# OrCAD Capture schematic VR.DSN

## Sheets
1 15 SENSOR: size B
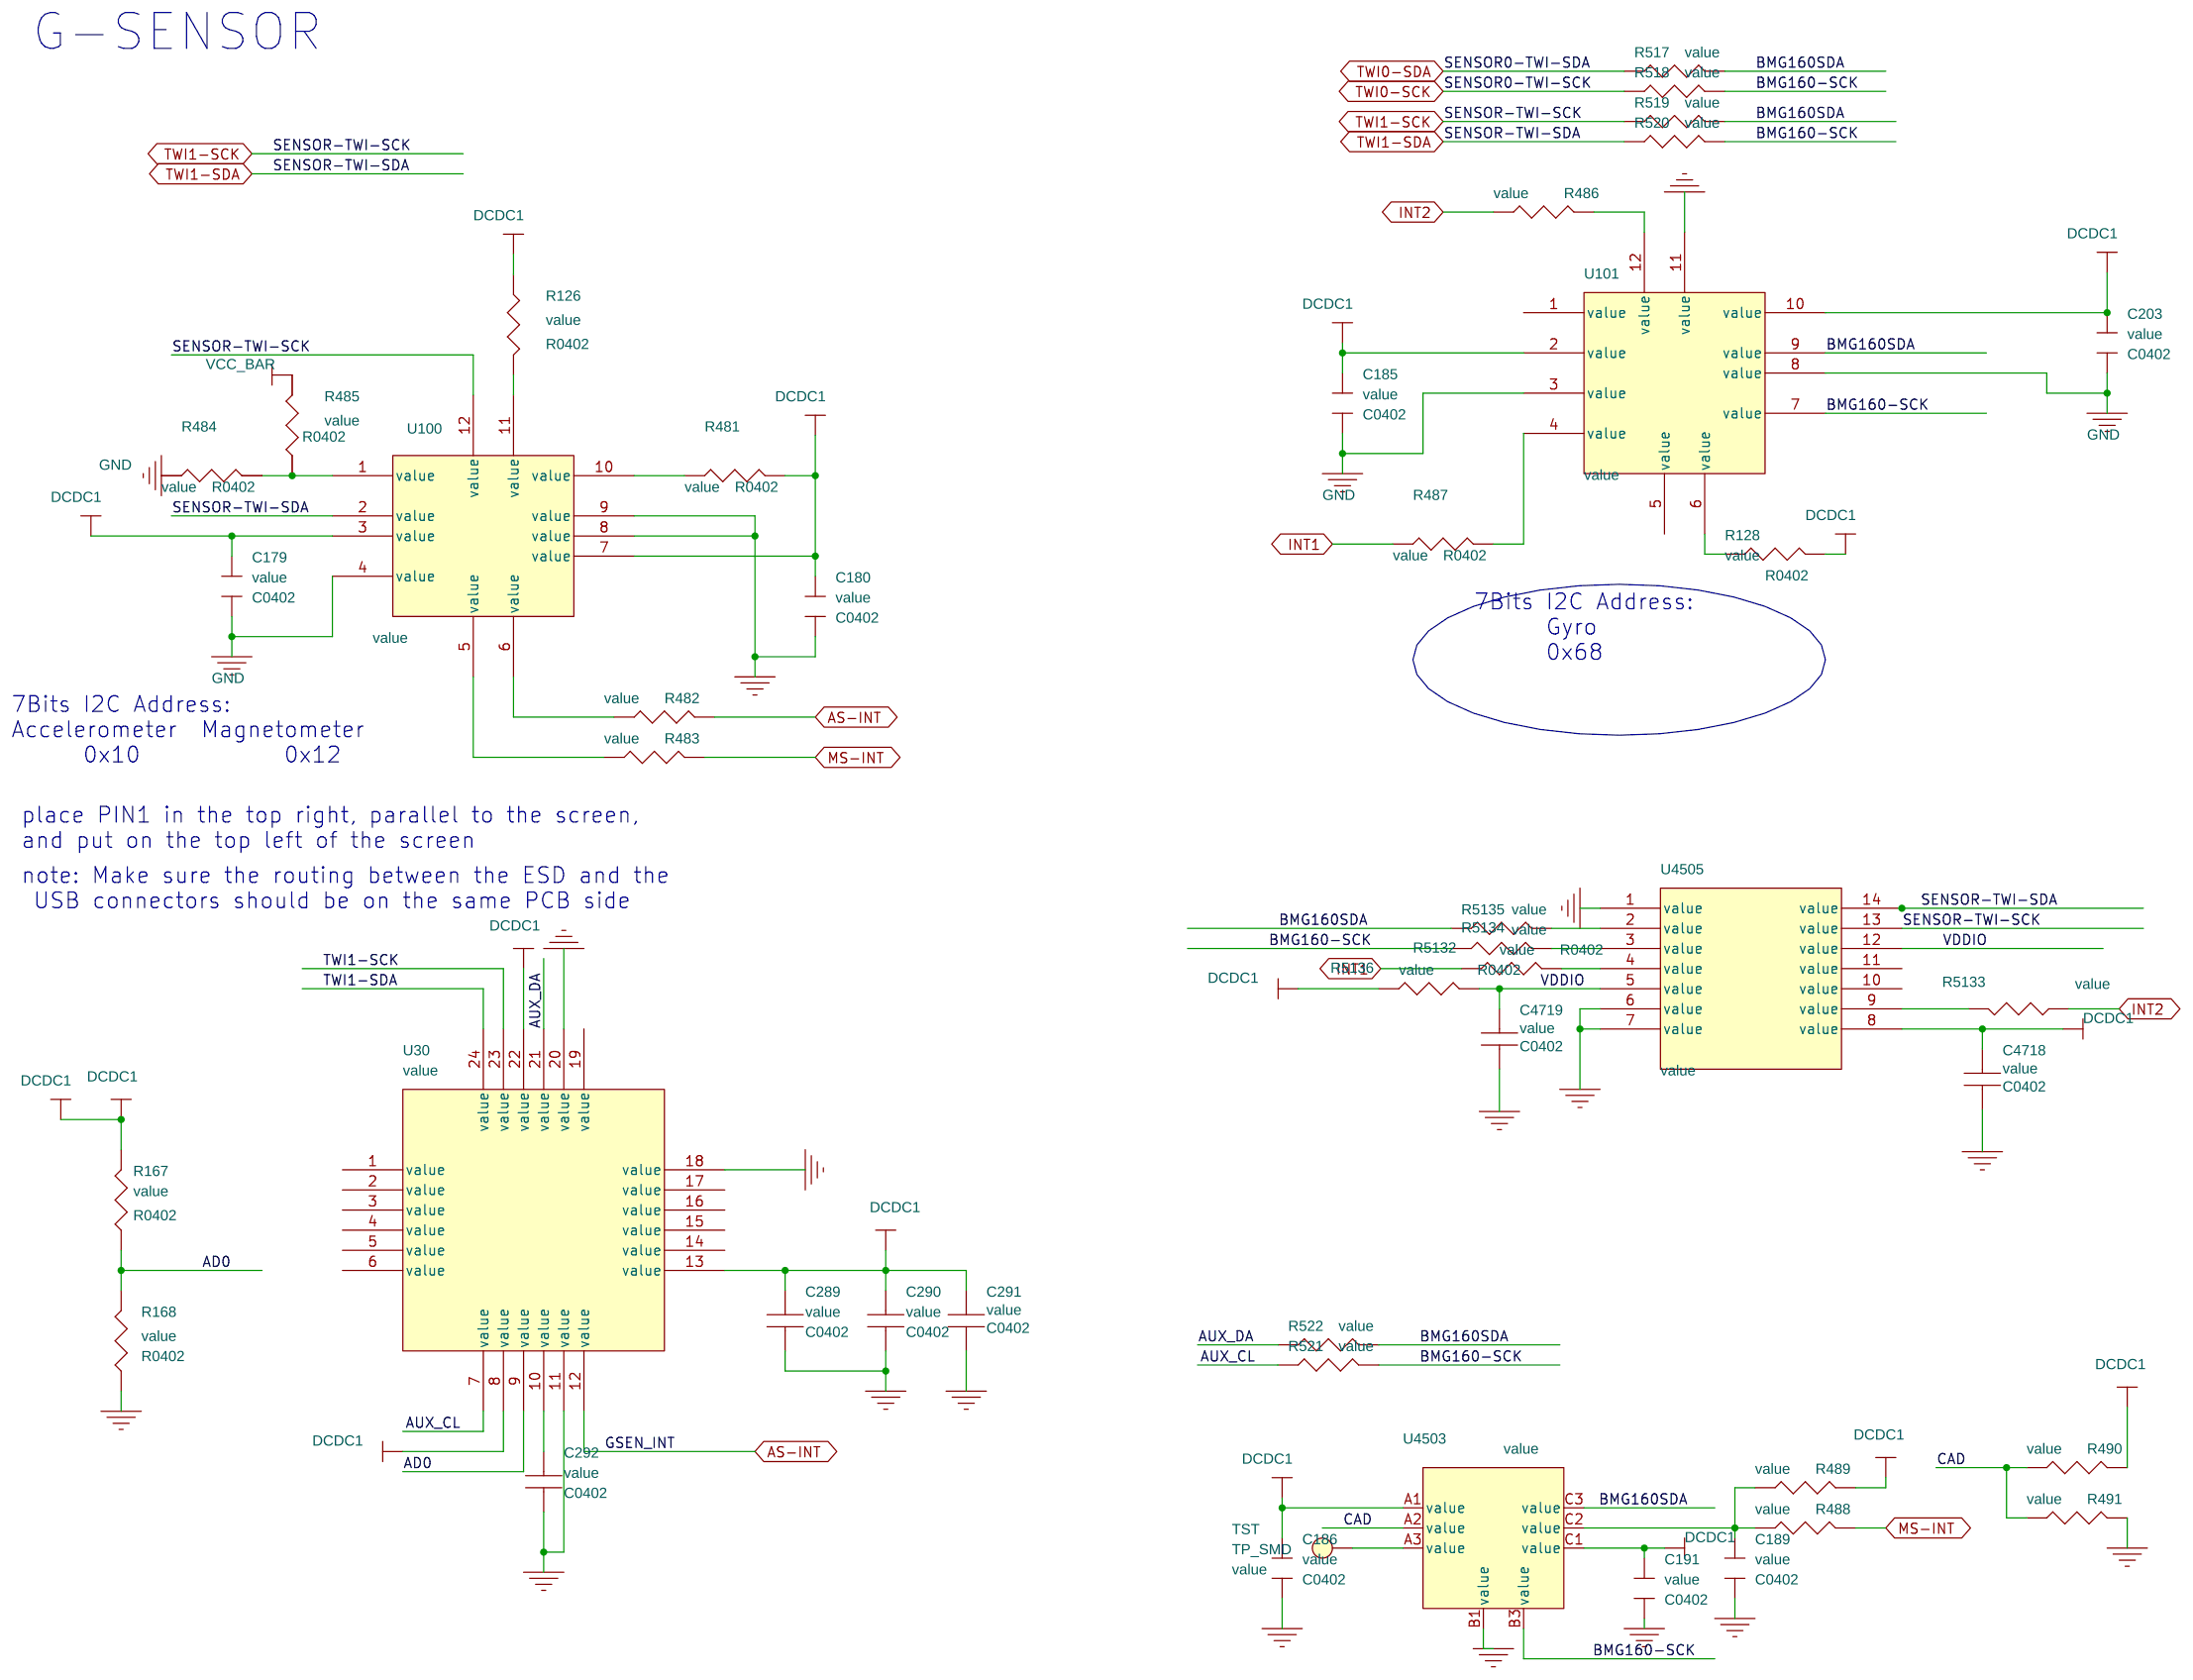
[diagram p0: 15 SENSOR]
2 09 CAMERA: size B
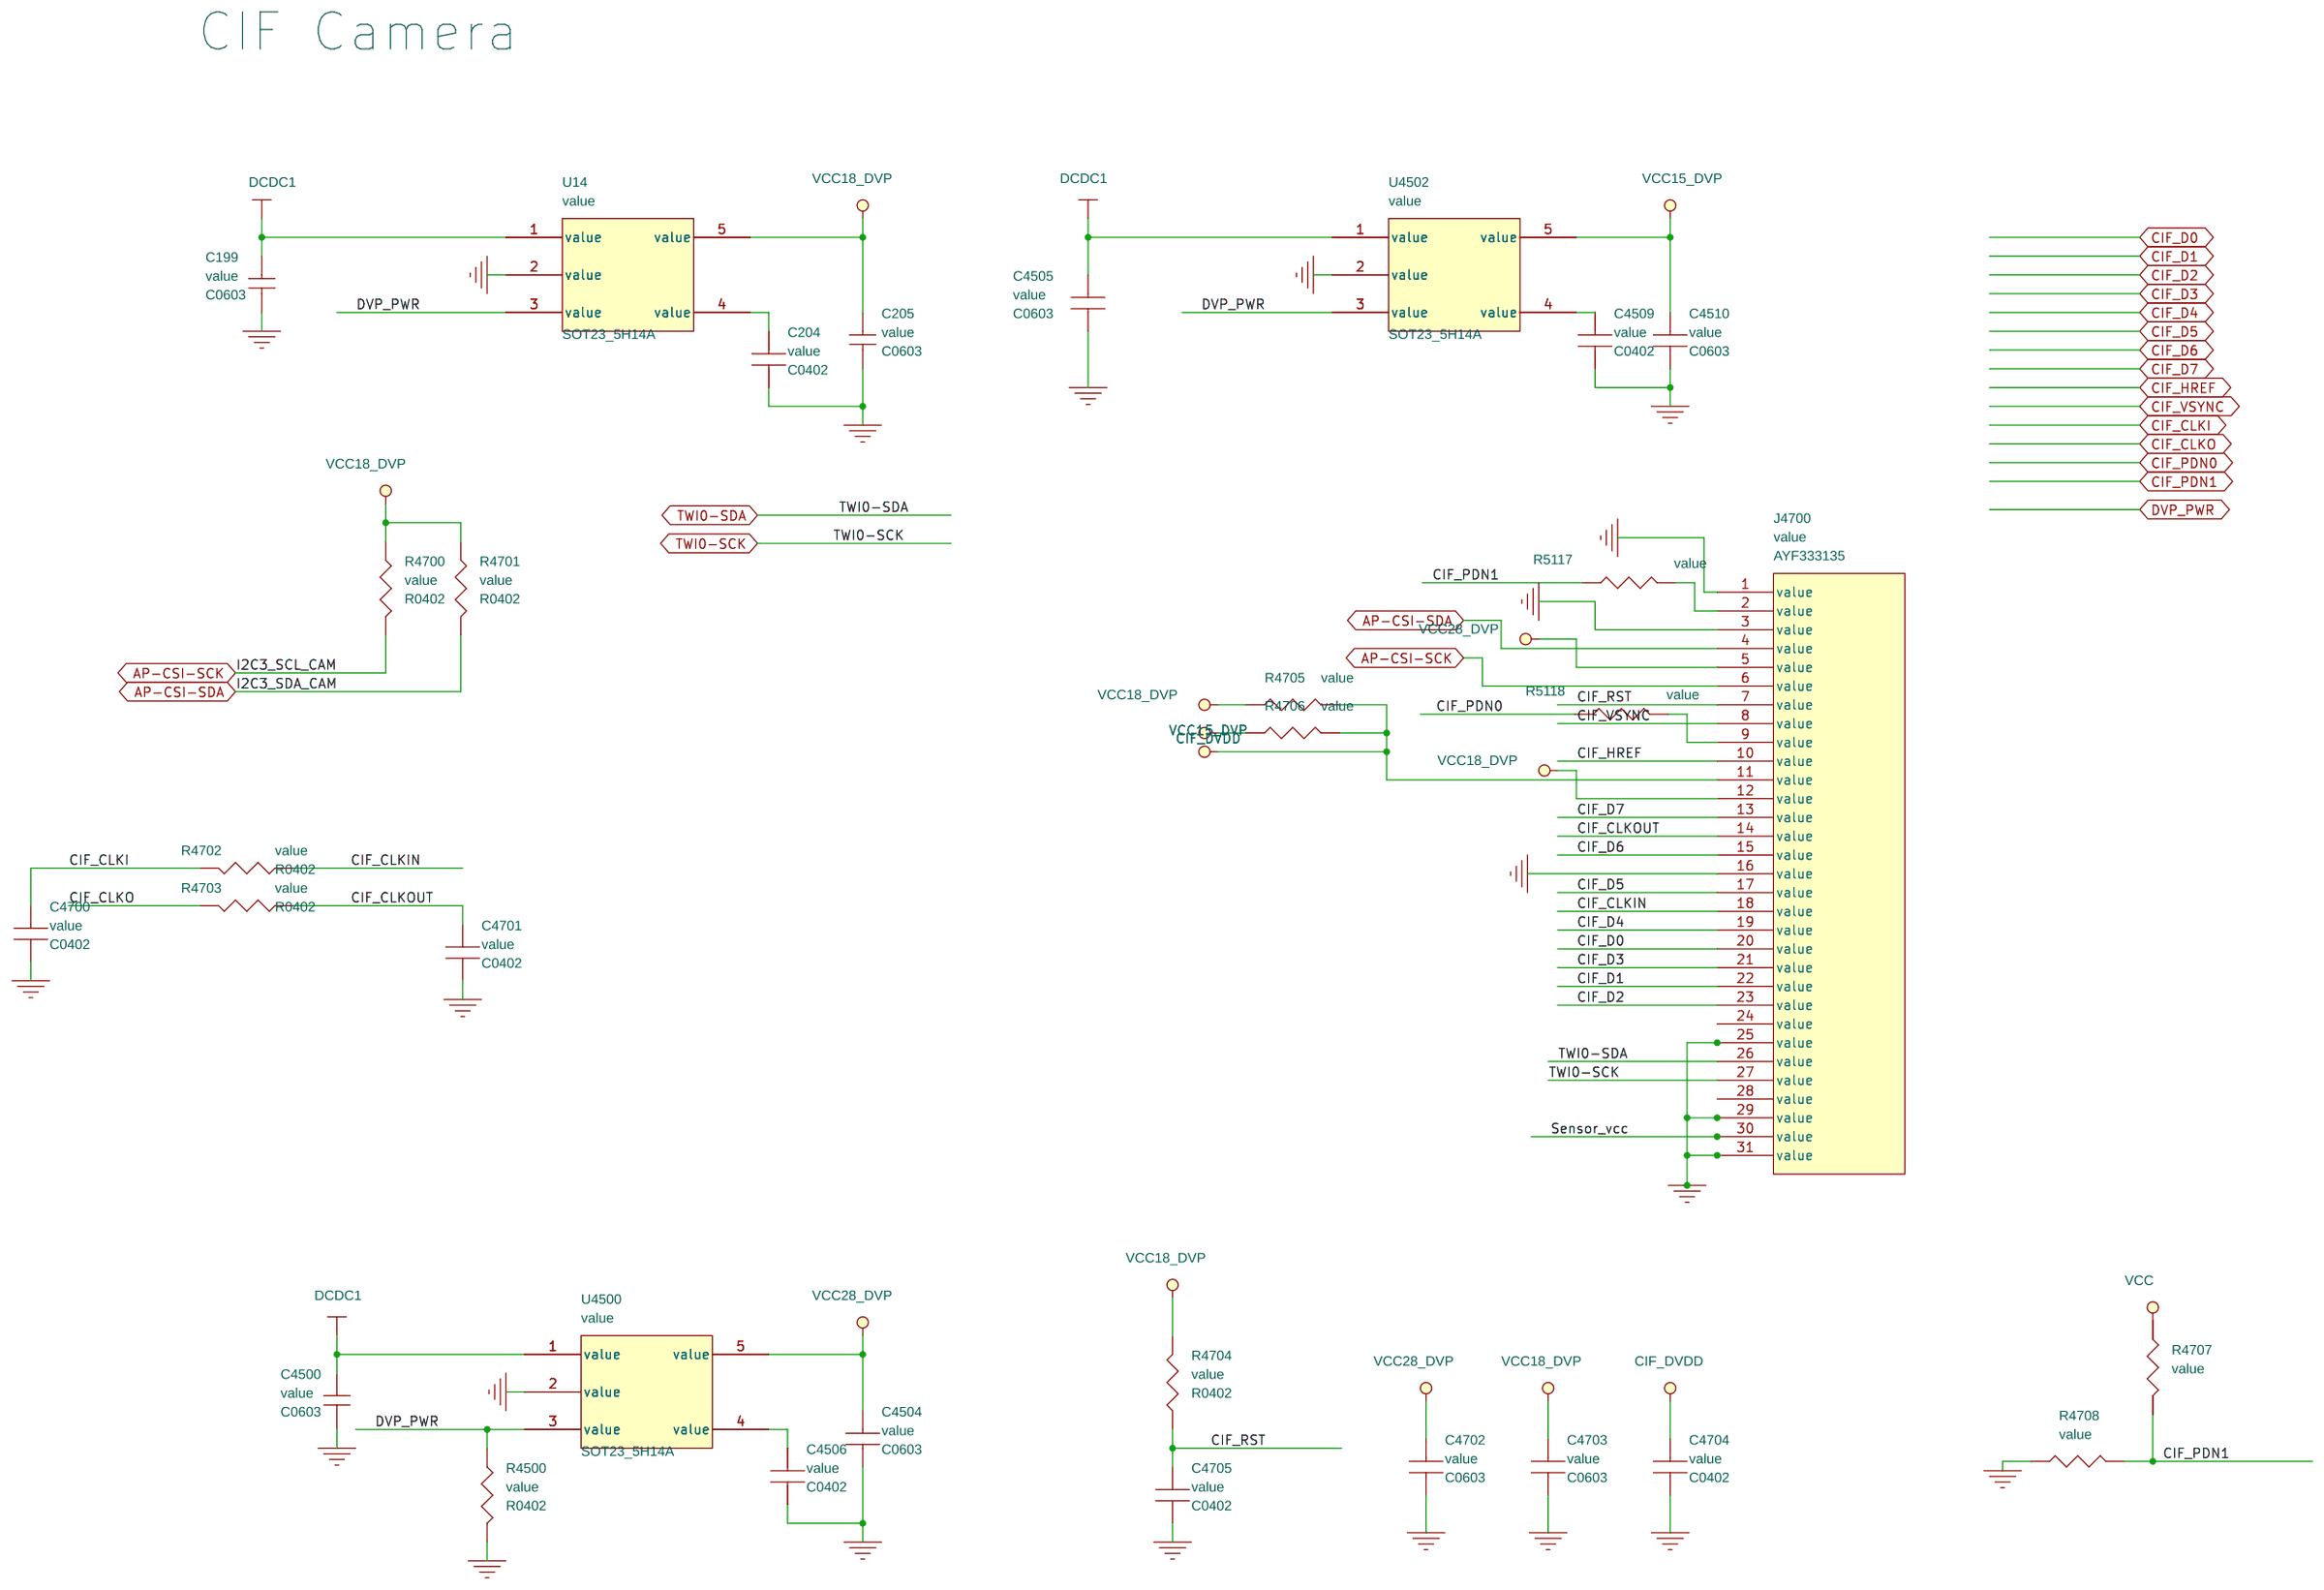
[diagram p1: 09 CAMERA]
3 14 TP: size A
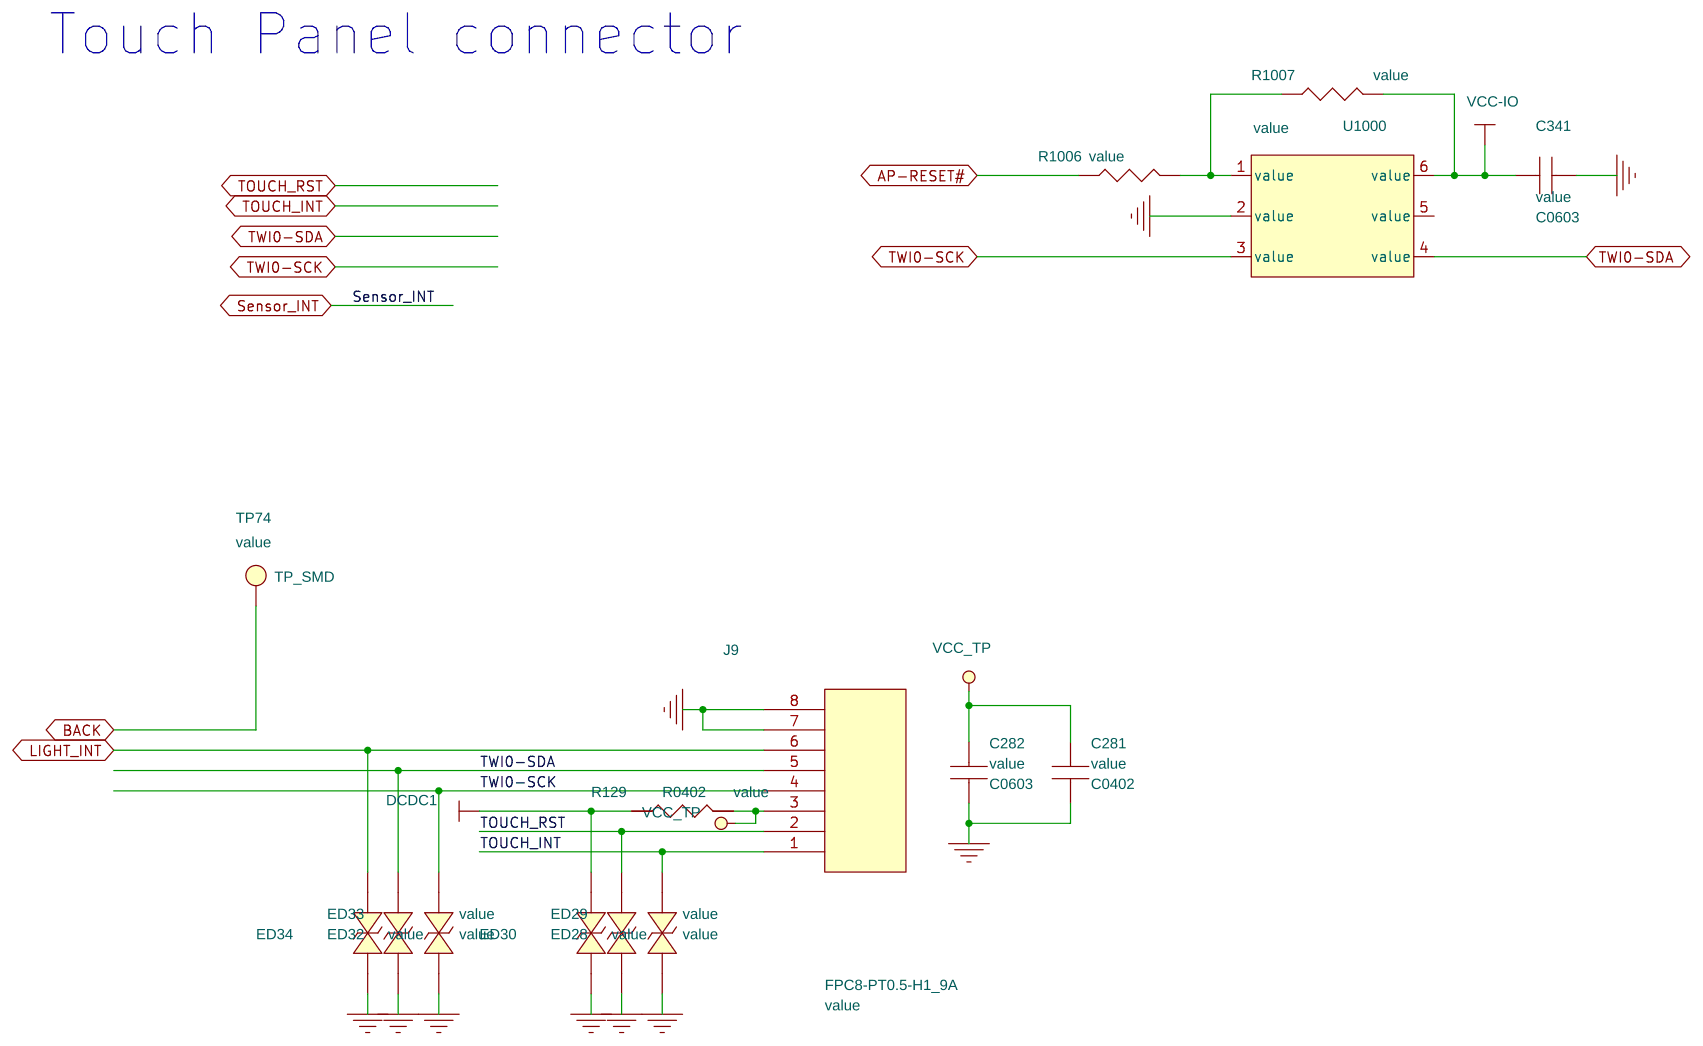
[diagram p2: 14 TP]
4 03 POWER TREE
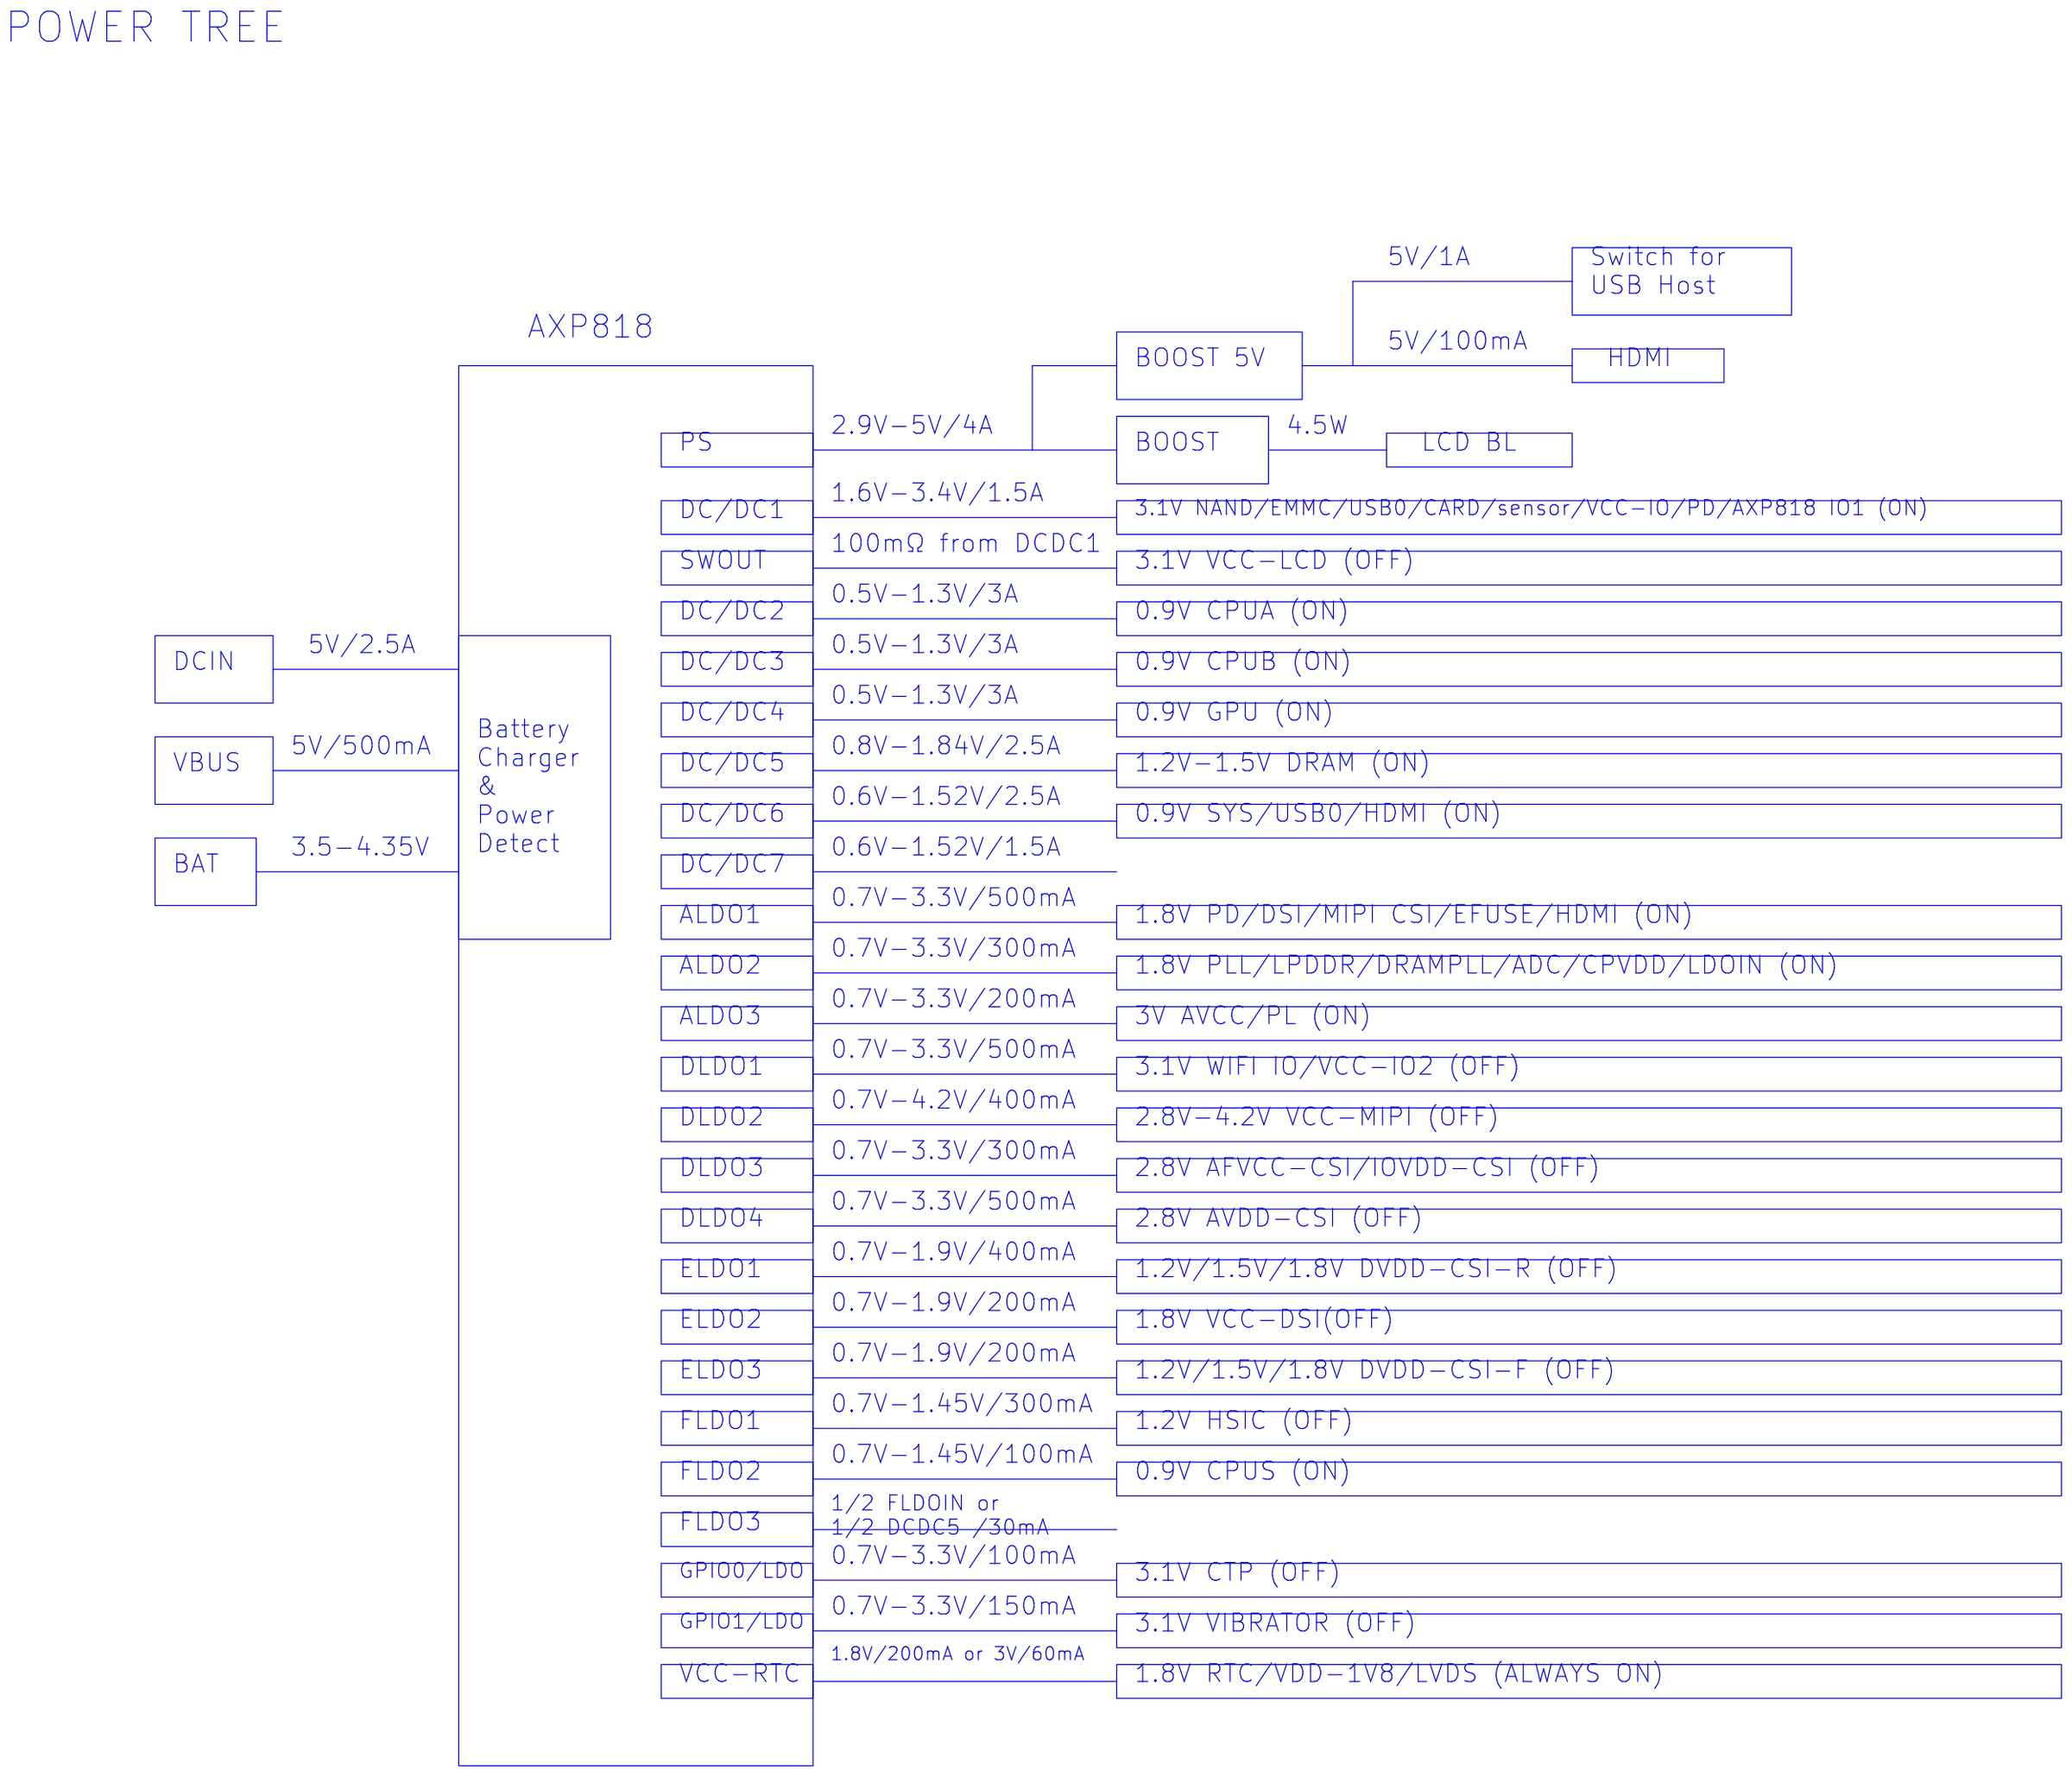
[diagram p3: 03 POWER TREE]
5 05 LPDDR3_32X1: size A3
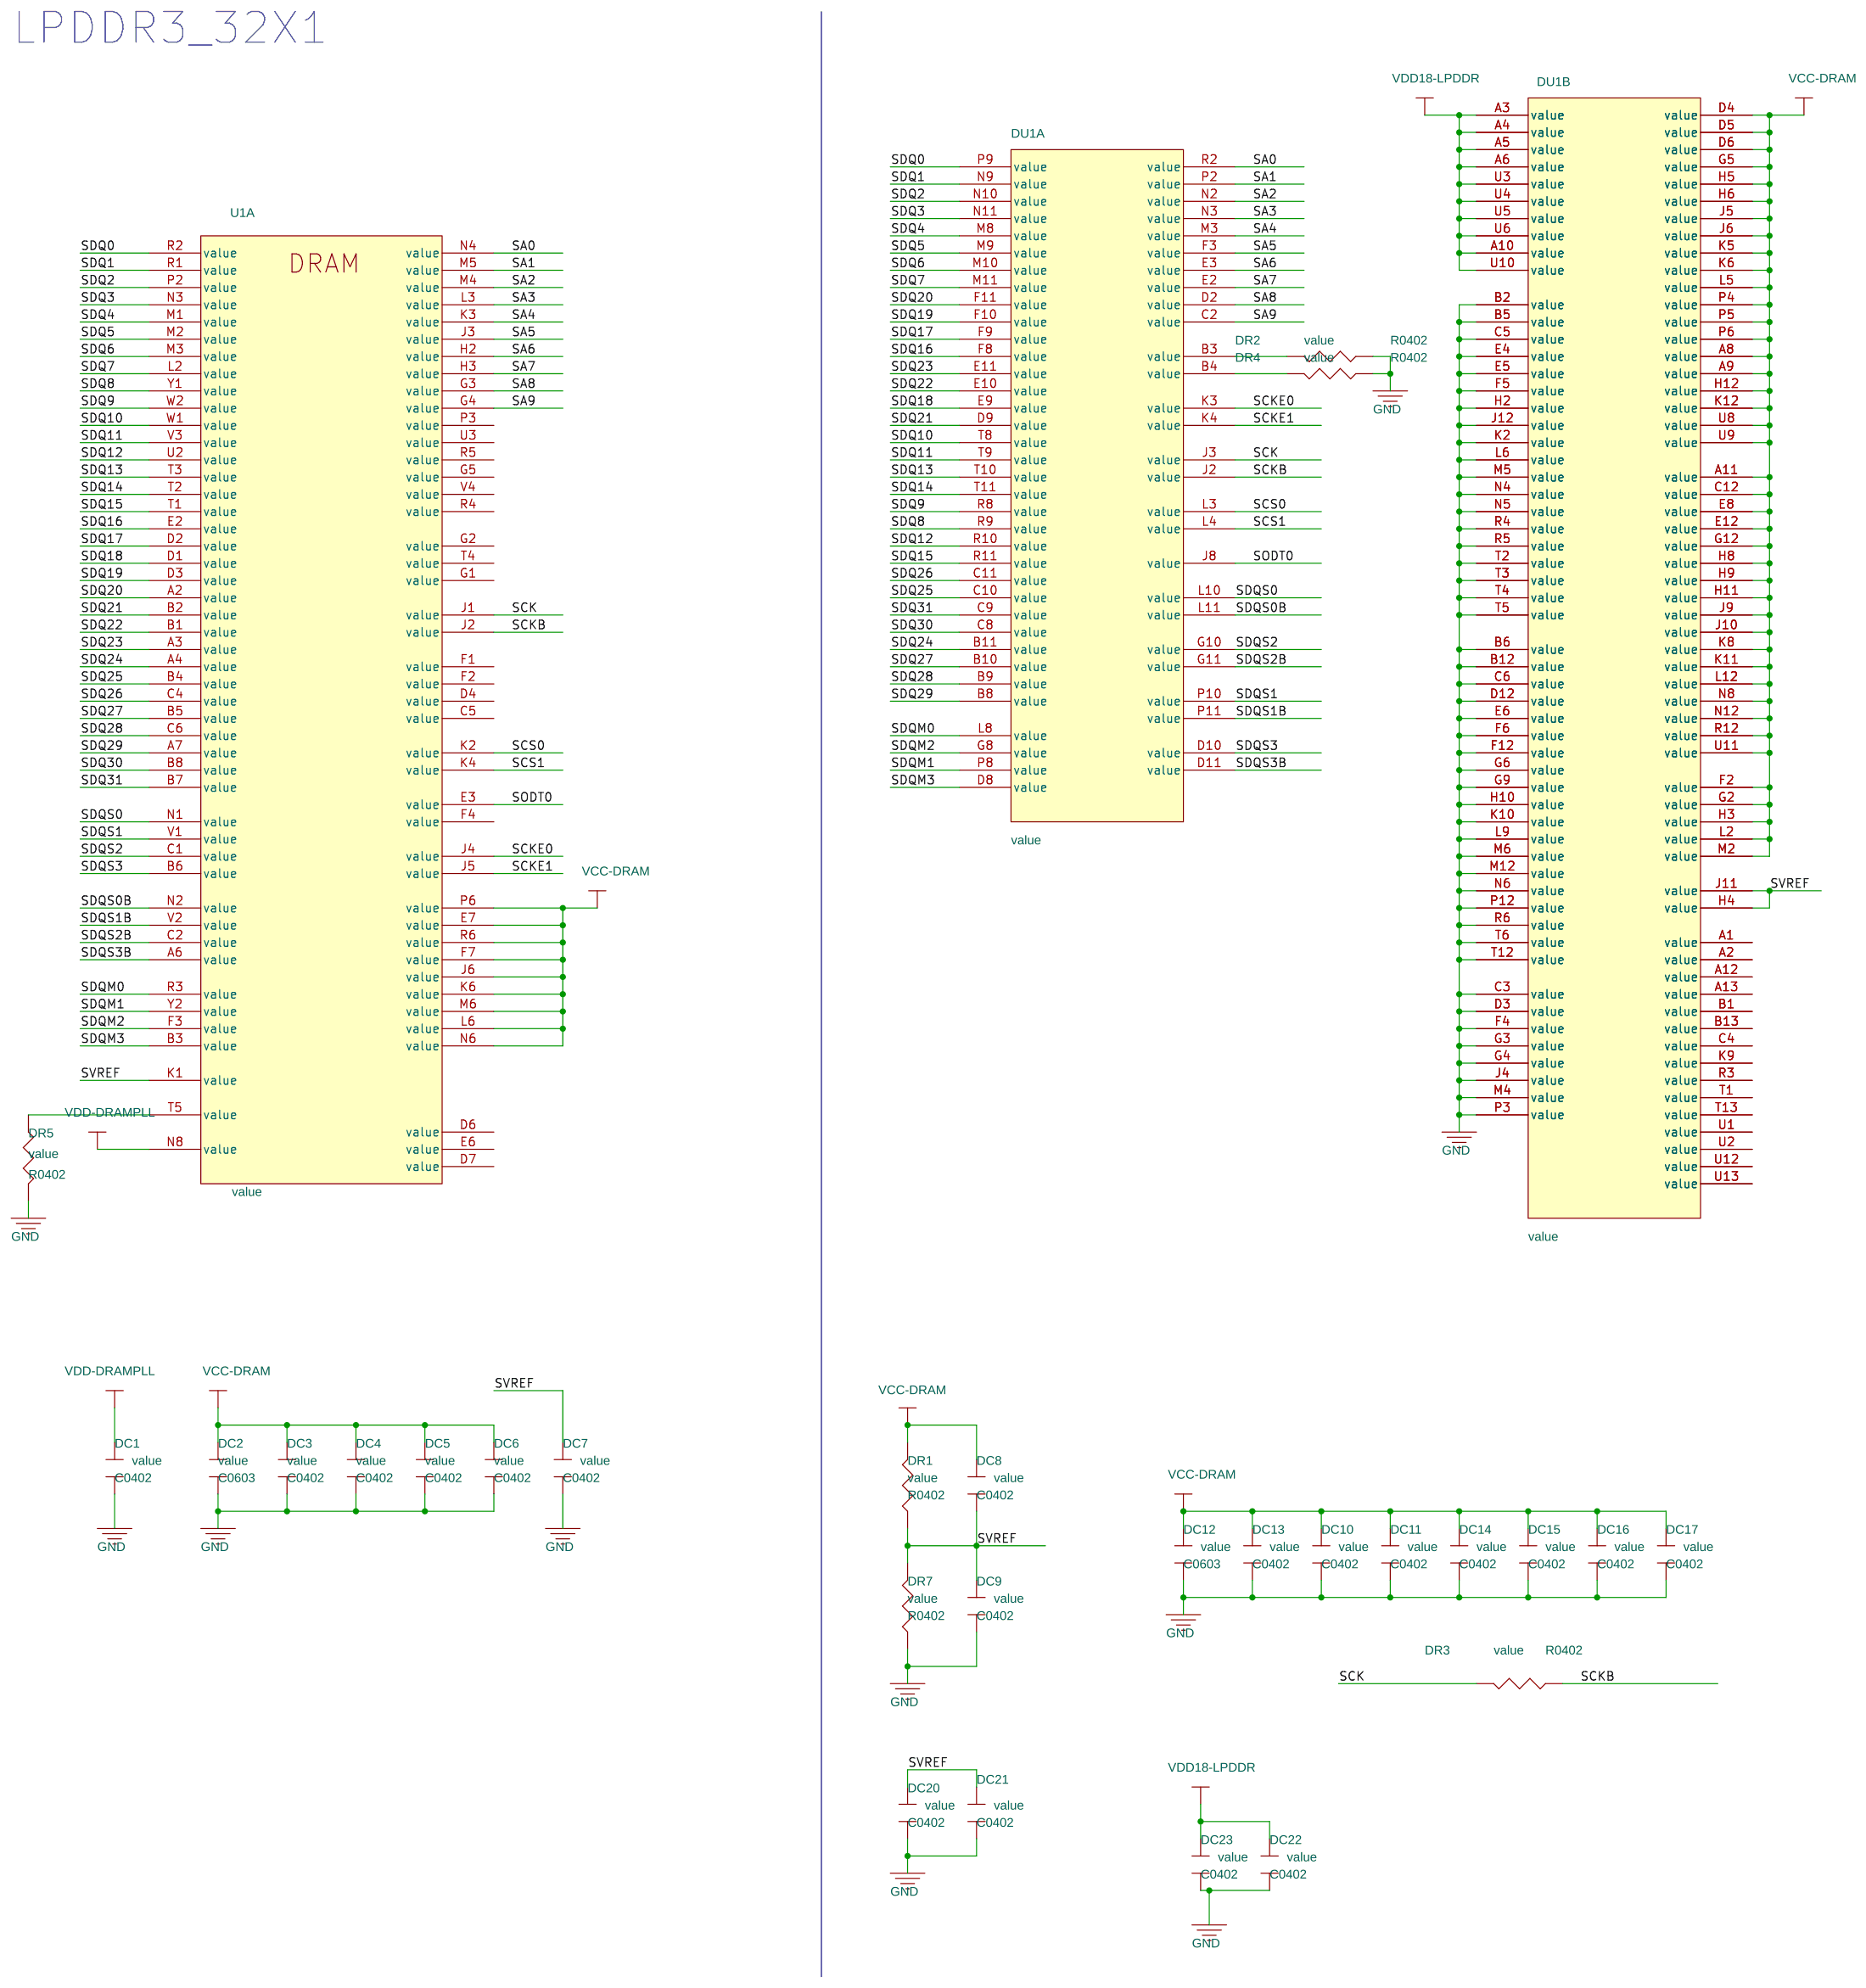
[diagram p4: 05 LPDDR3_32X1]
6 06 CPU: size A3
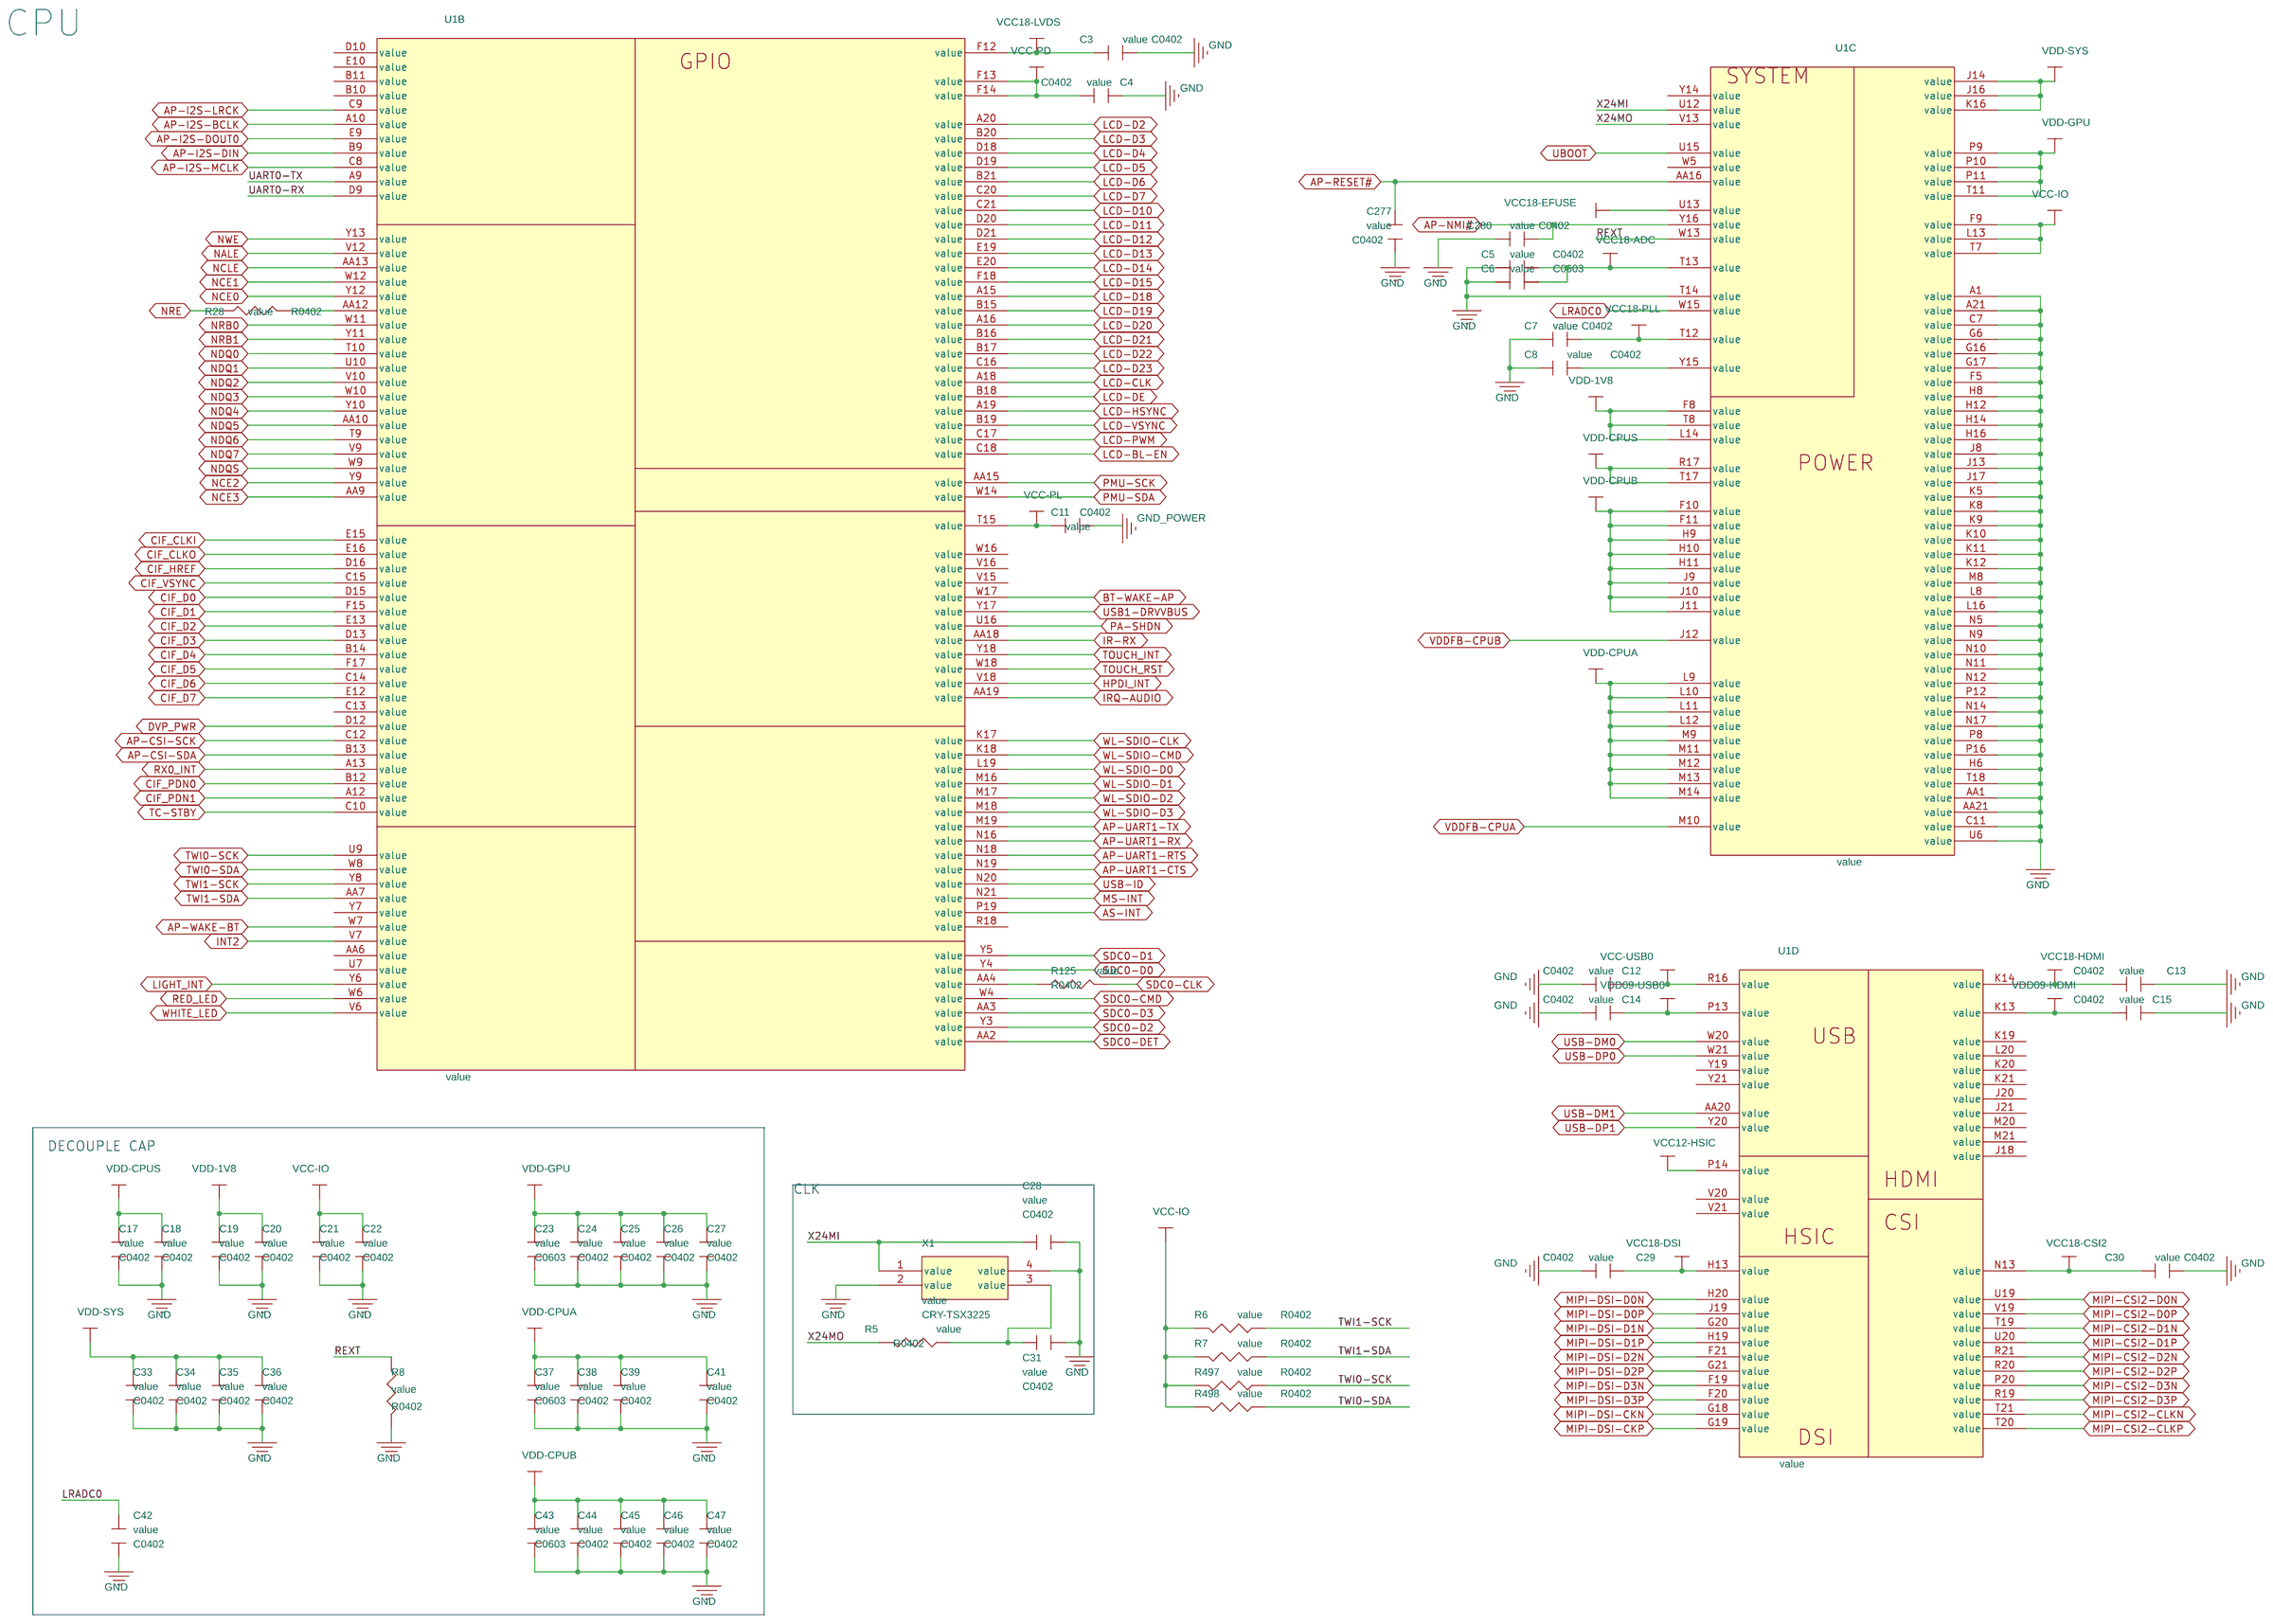
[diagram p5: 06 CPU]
7 07 POWER: size A3
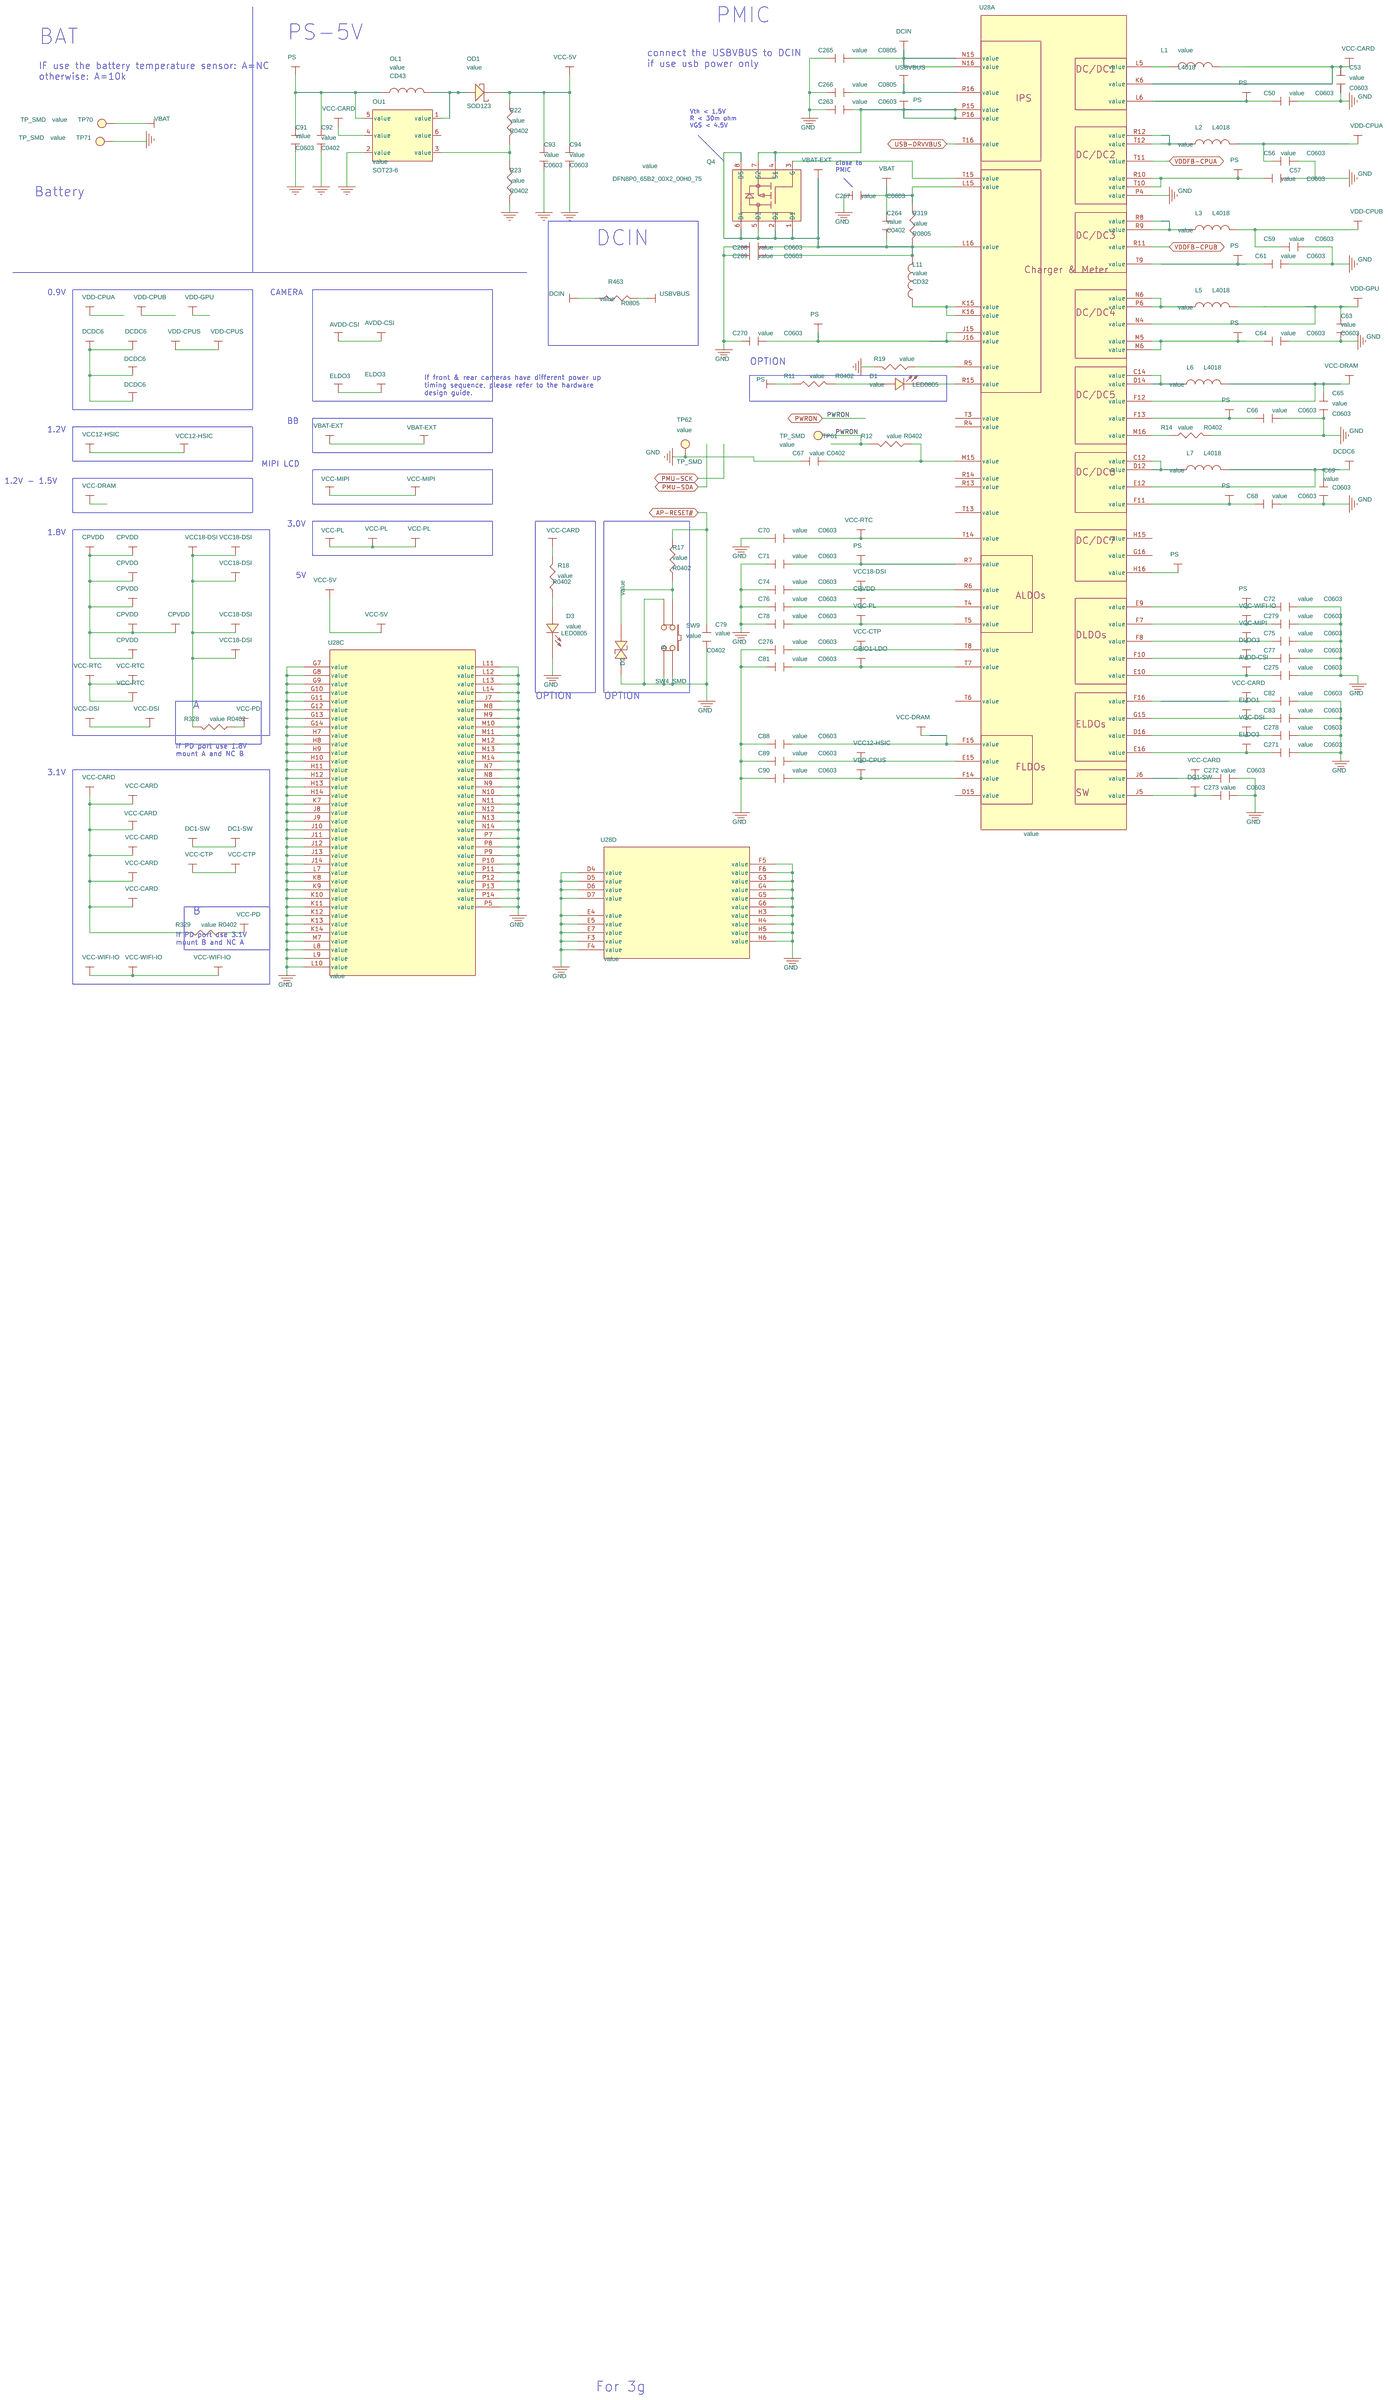
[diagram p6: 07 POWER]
8 08 NAND-eMMC: size A3
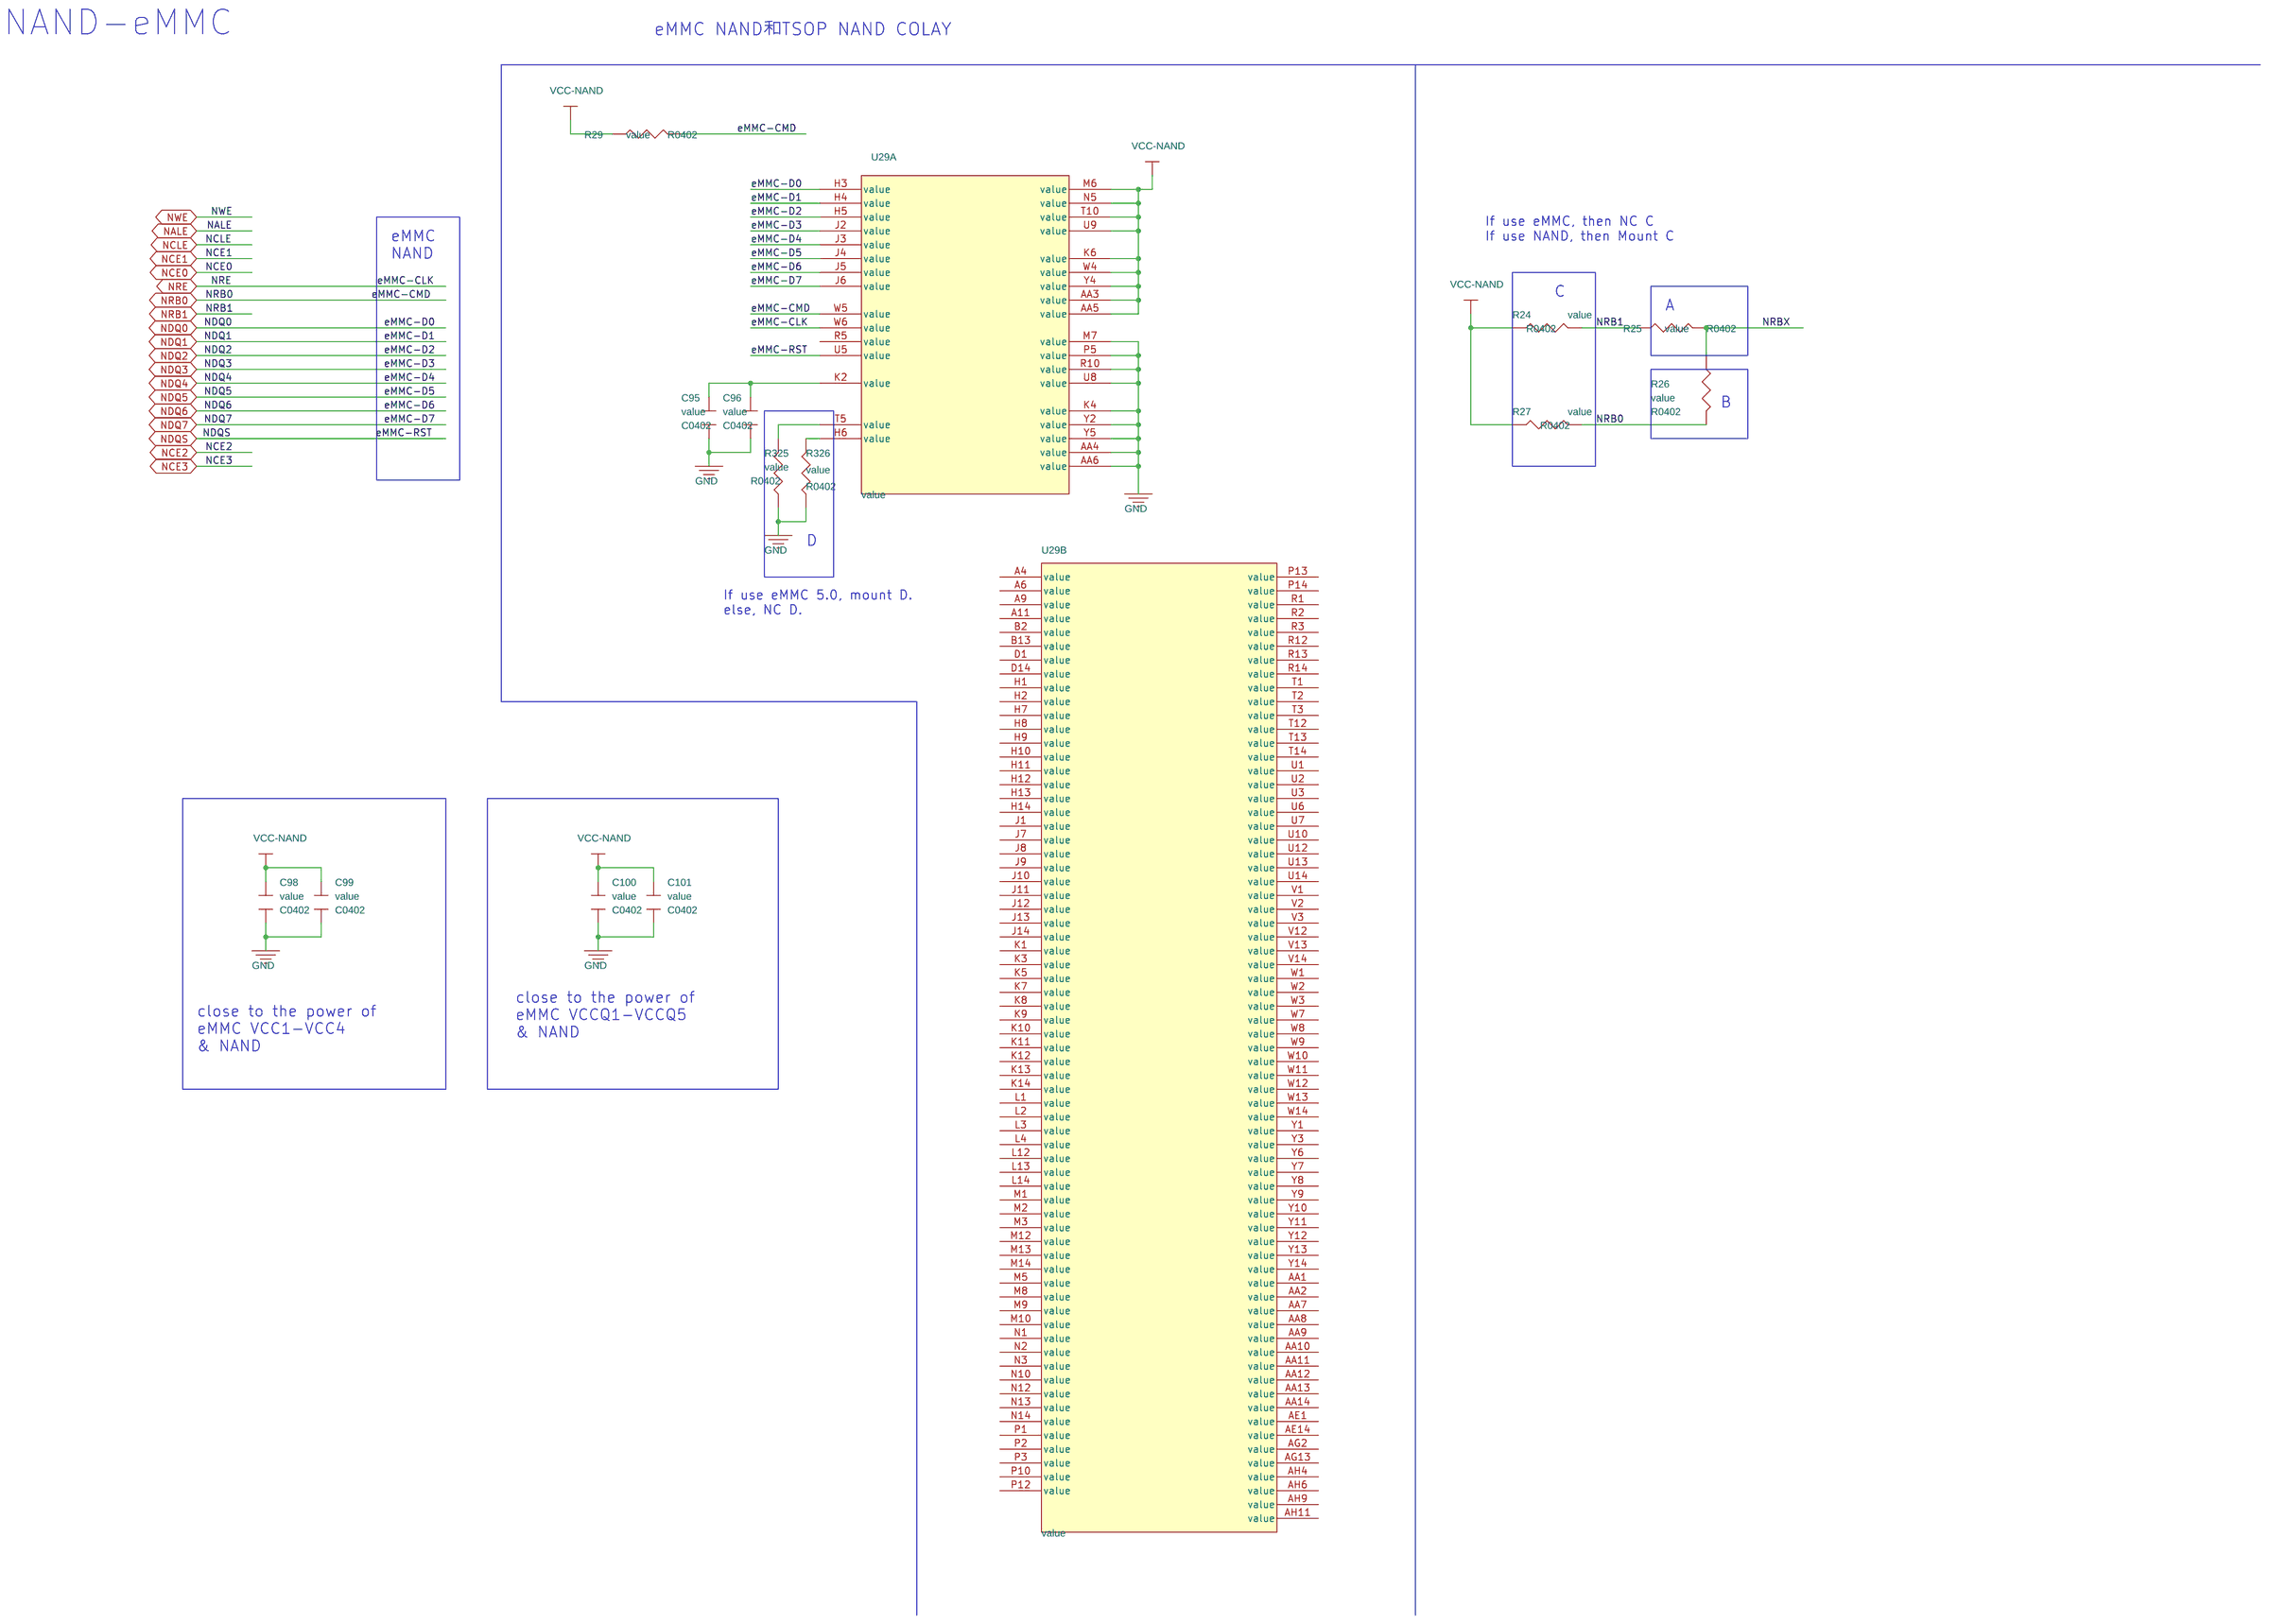
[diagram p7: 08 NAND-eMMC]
9 10 MIPI DSI: size Custom
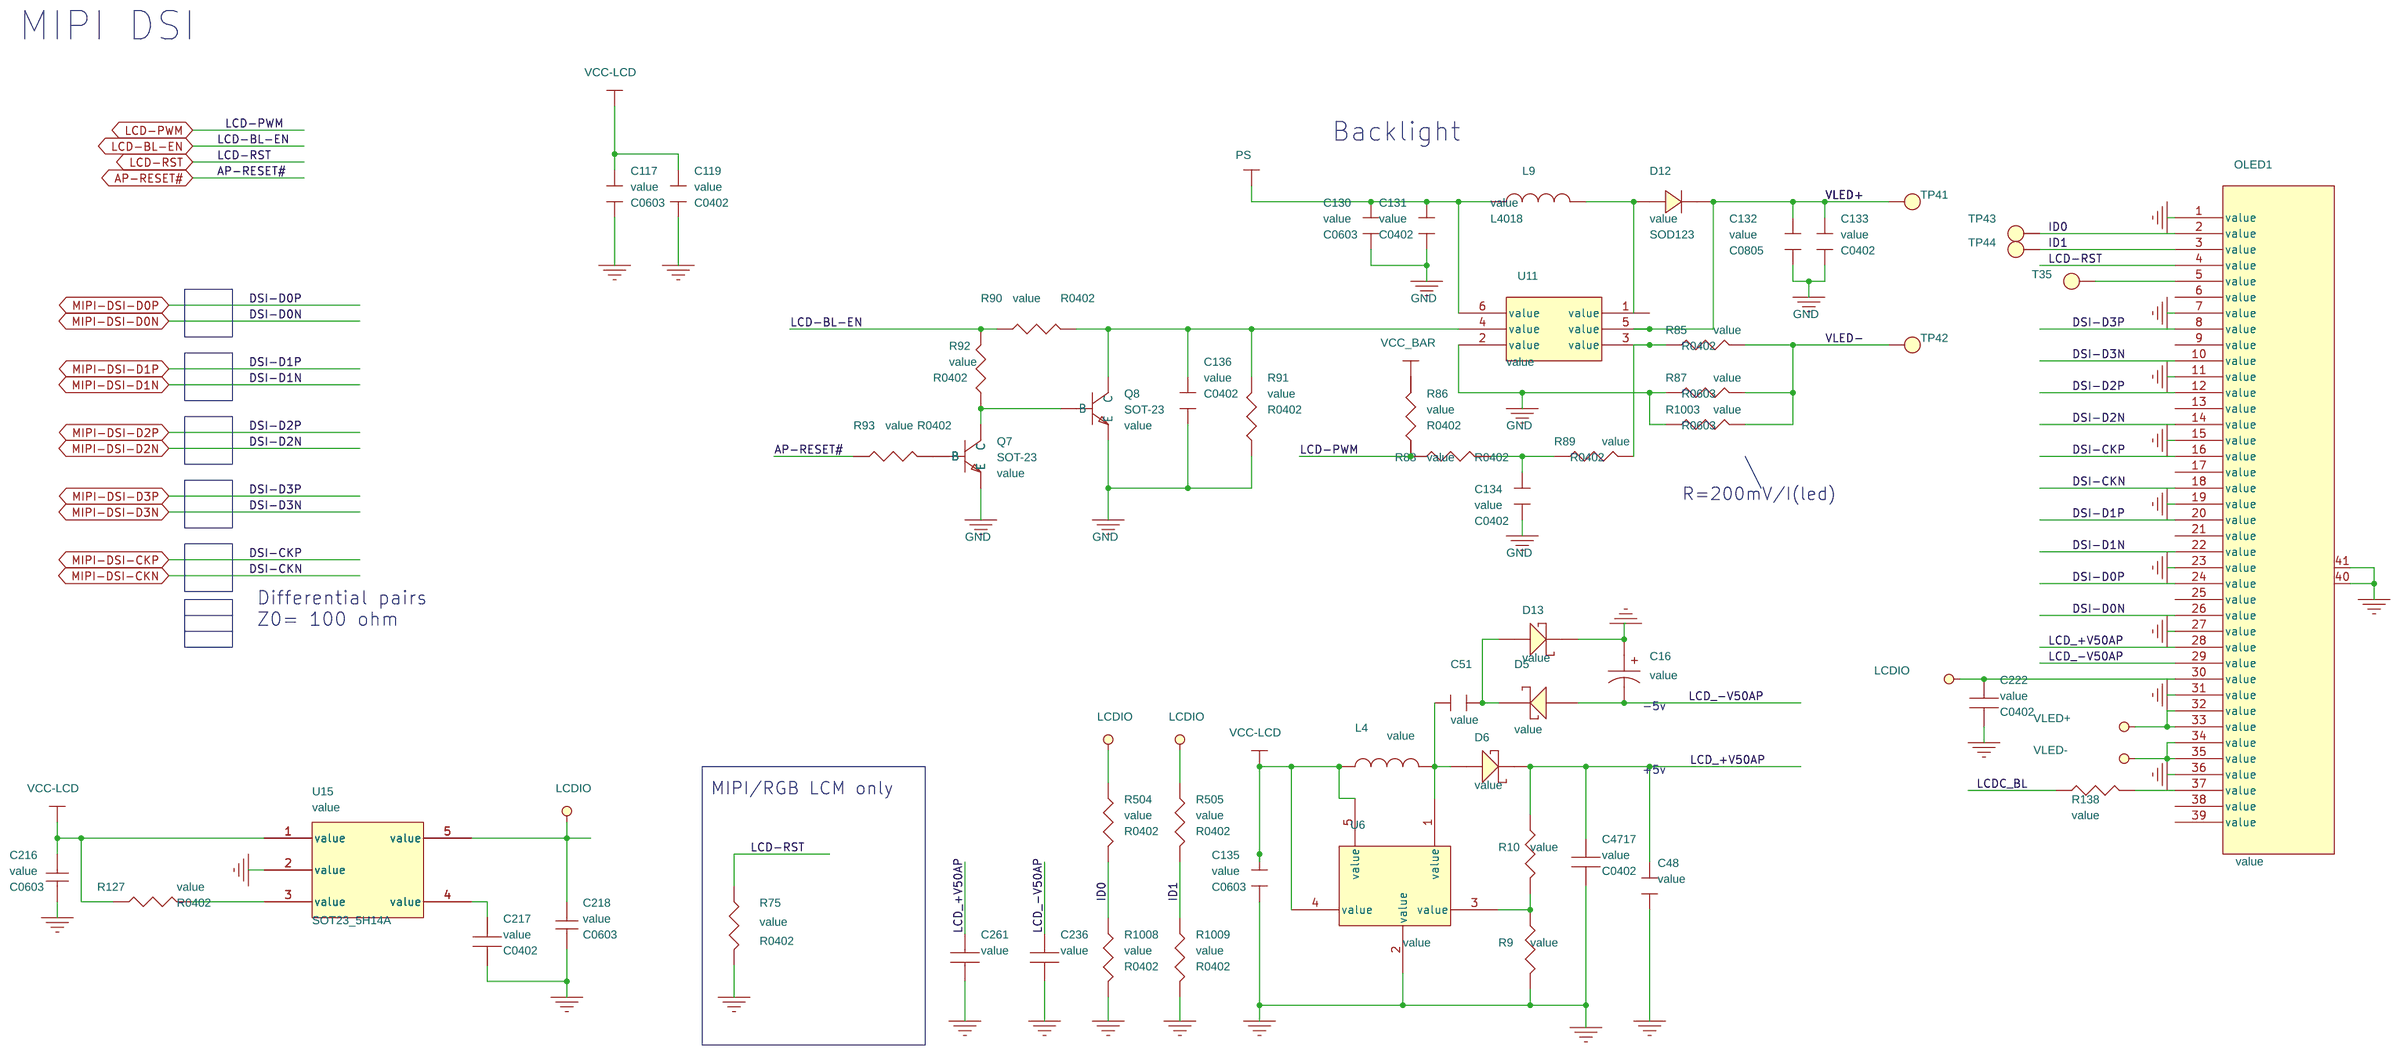
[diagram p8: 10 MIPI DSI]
10 11 CARD-SENSOR-VIBRATOR-KEY-OTG: size A3
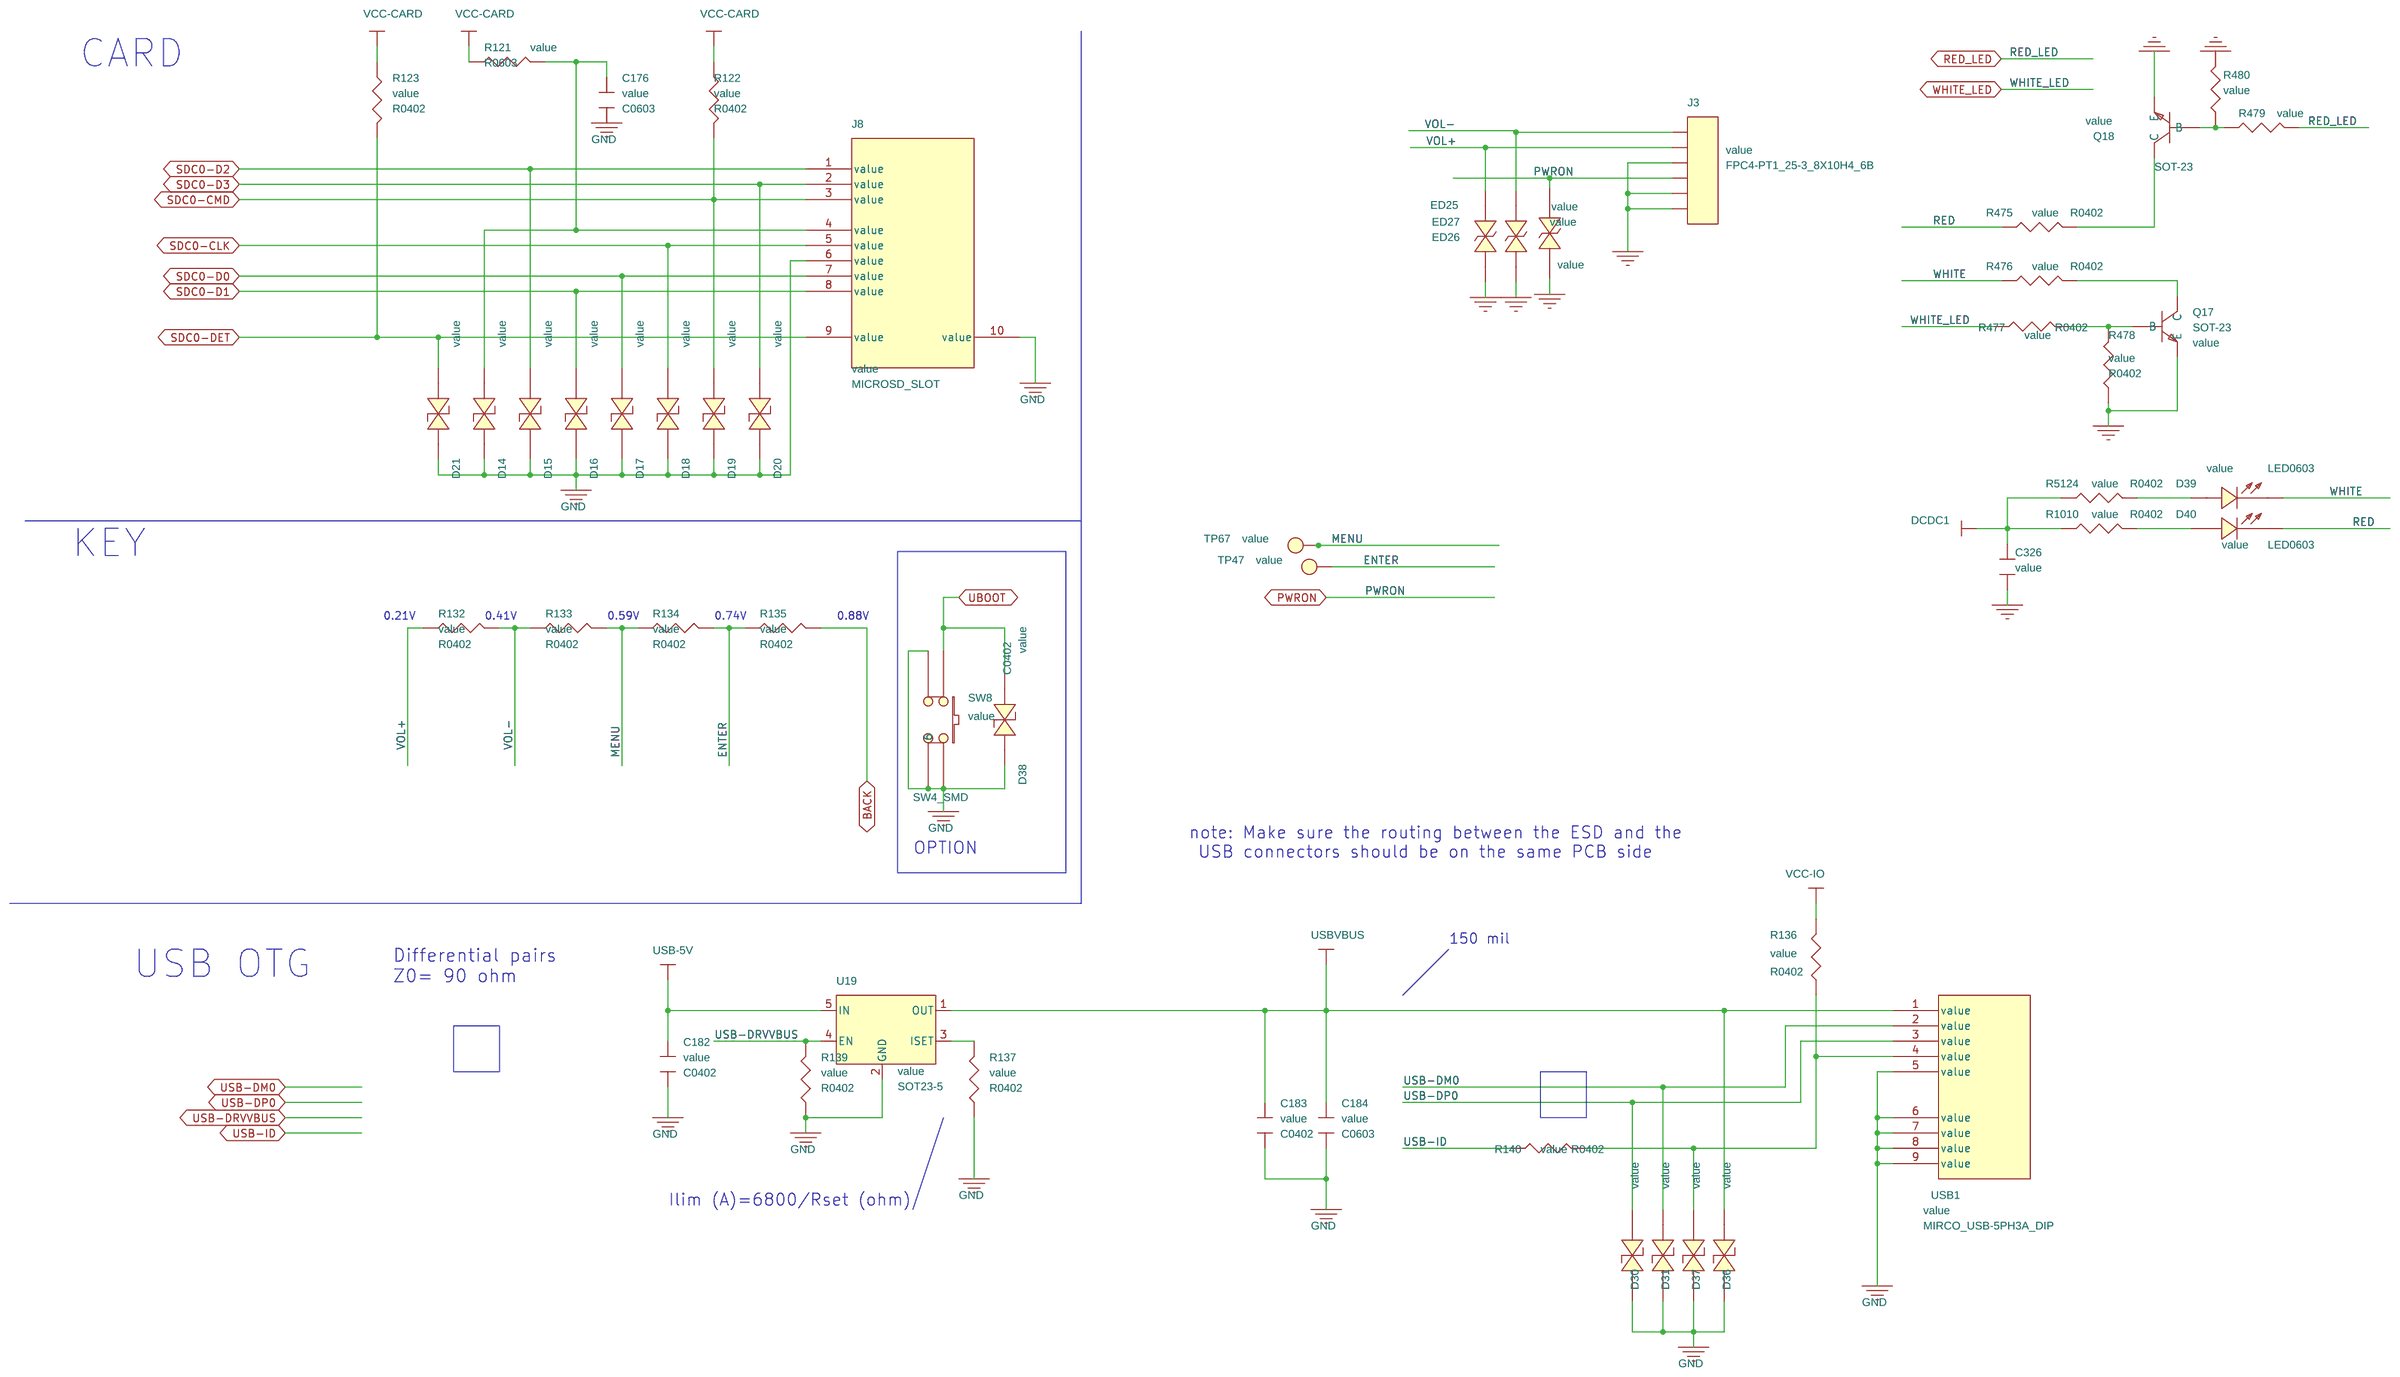
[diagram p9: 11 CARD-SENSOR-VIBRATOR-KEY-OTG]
11 12 CODEC: size A3
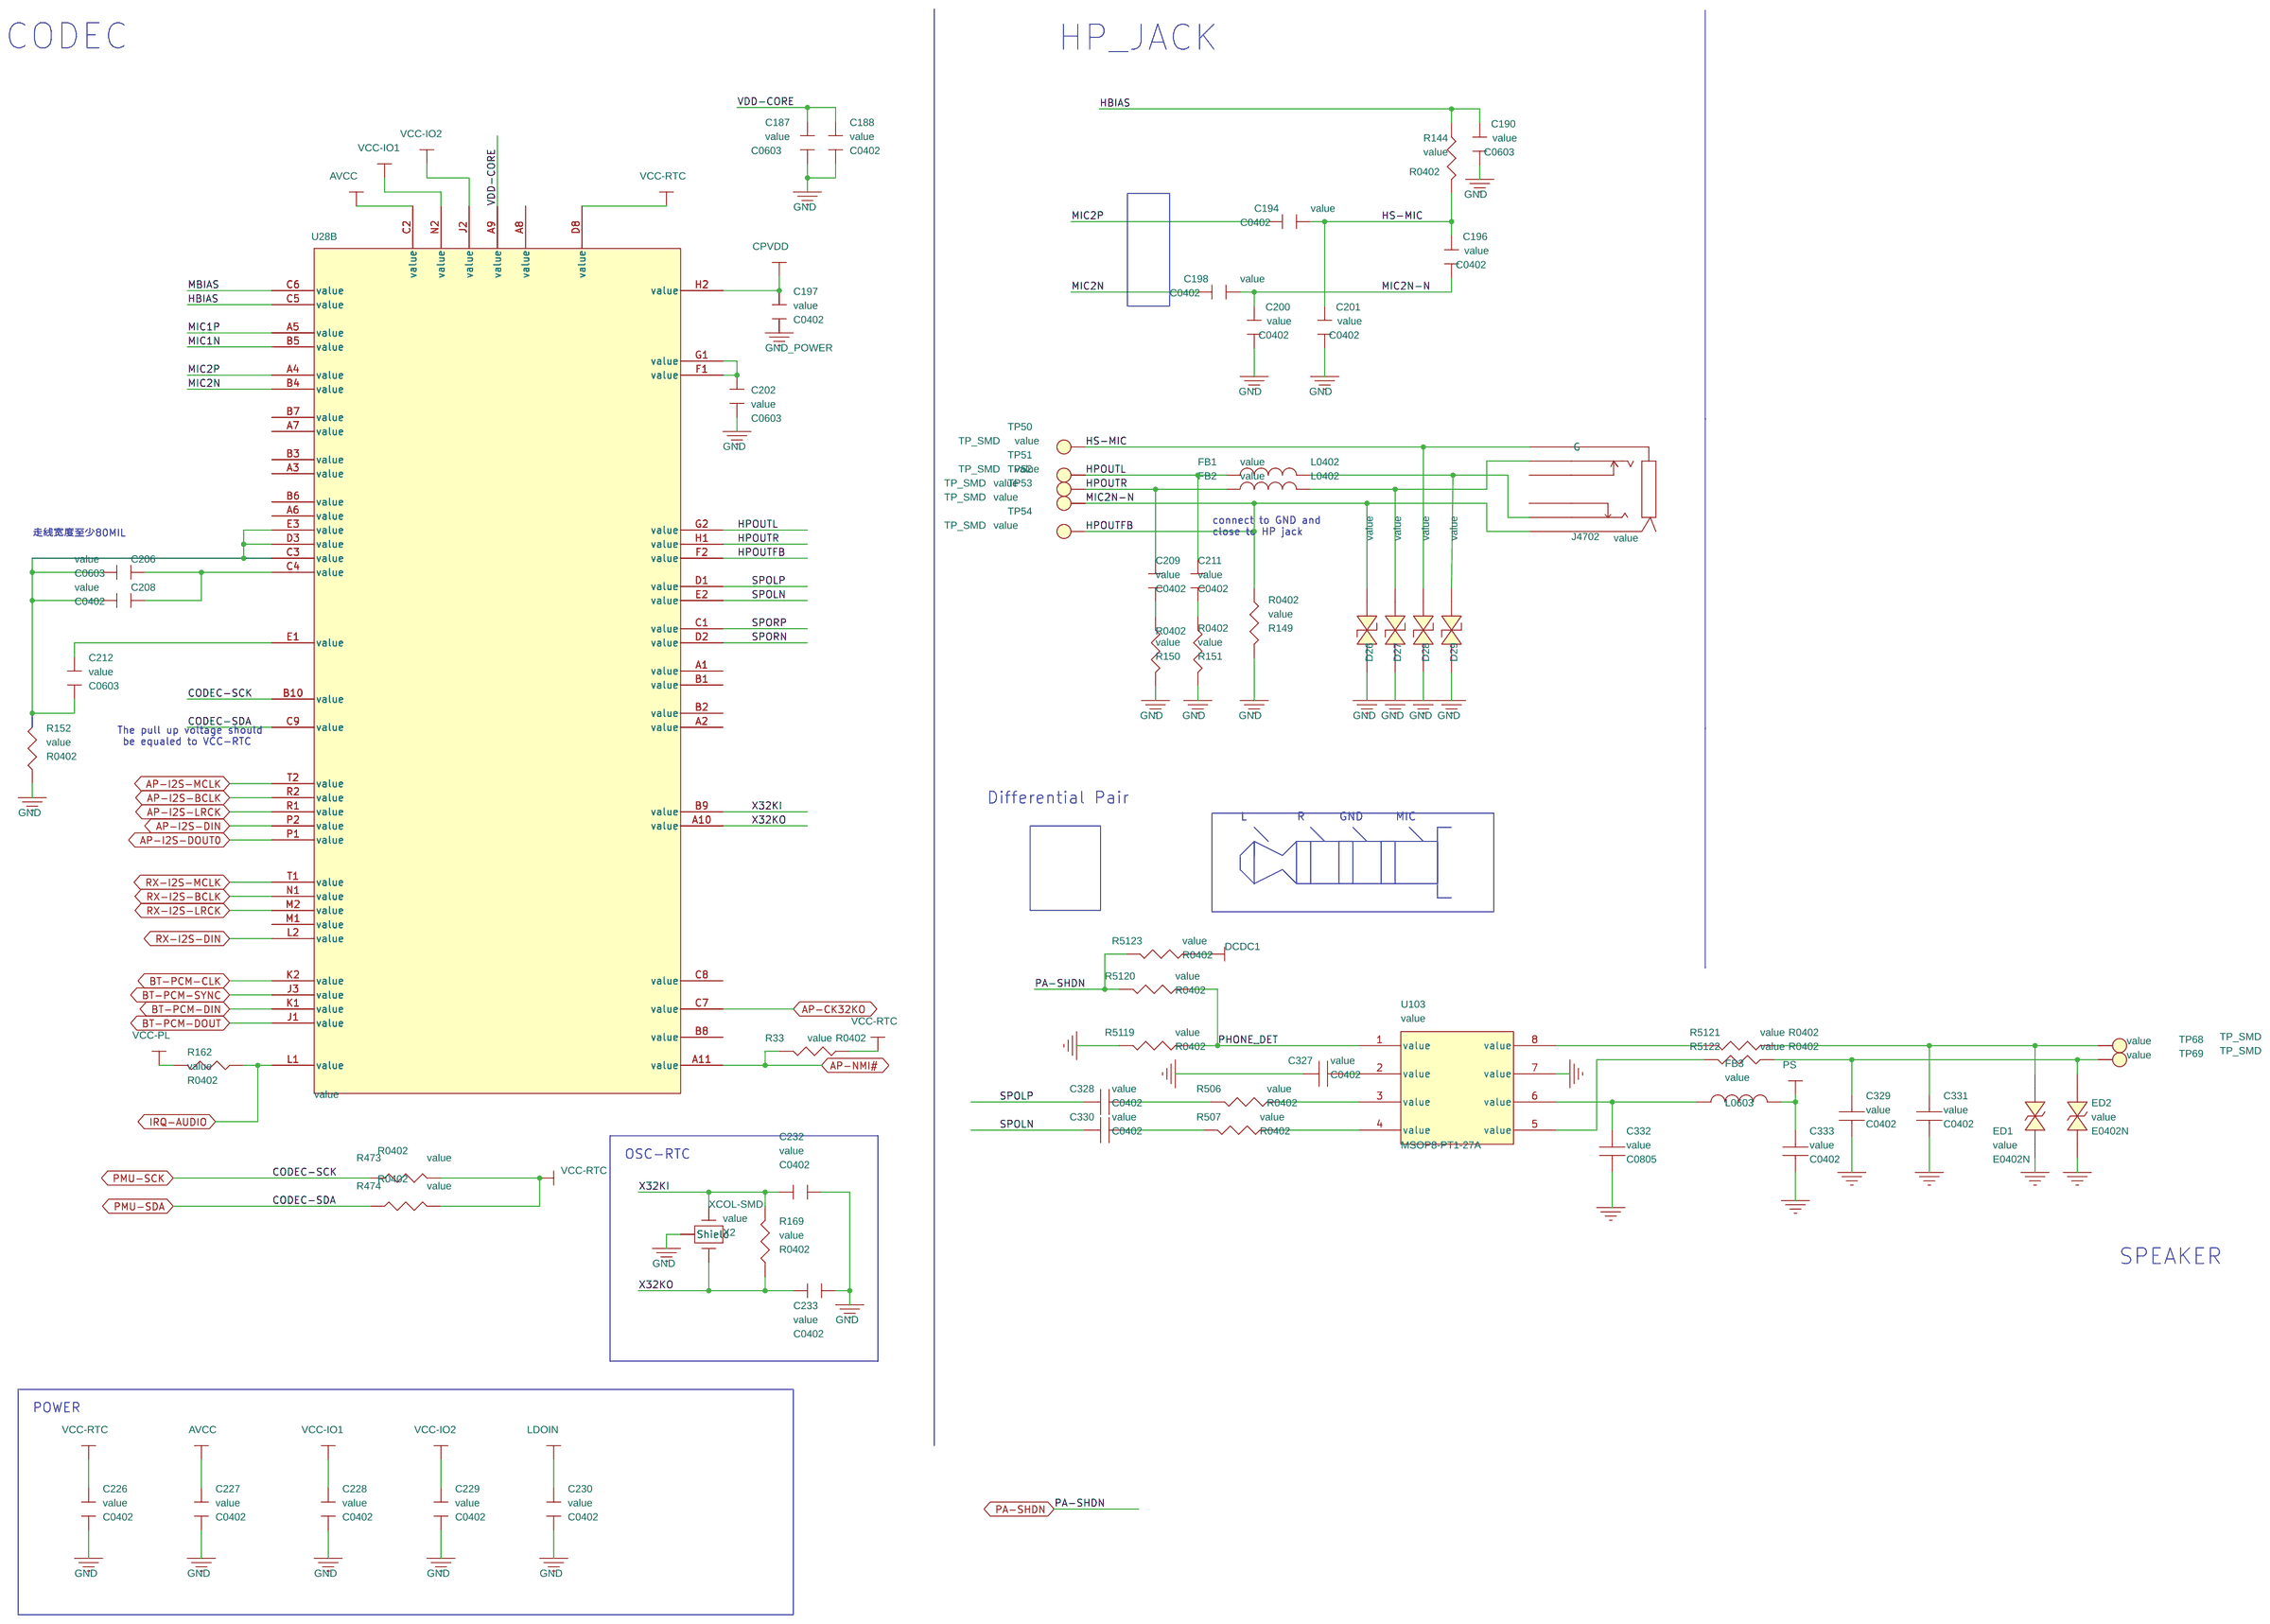
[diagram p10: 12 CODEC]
12 13 WIFI+BT: size A3
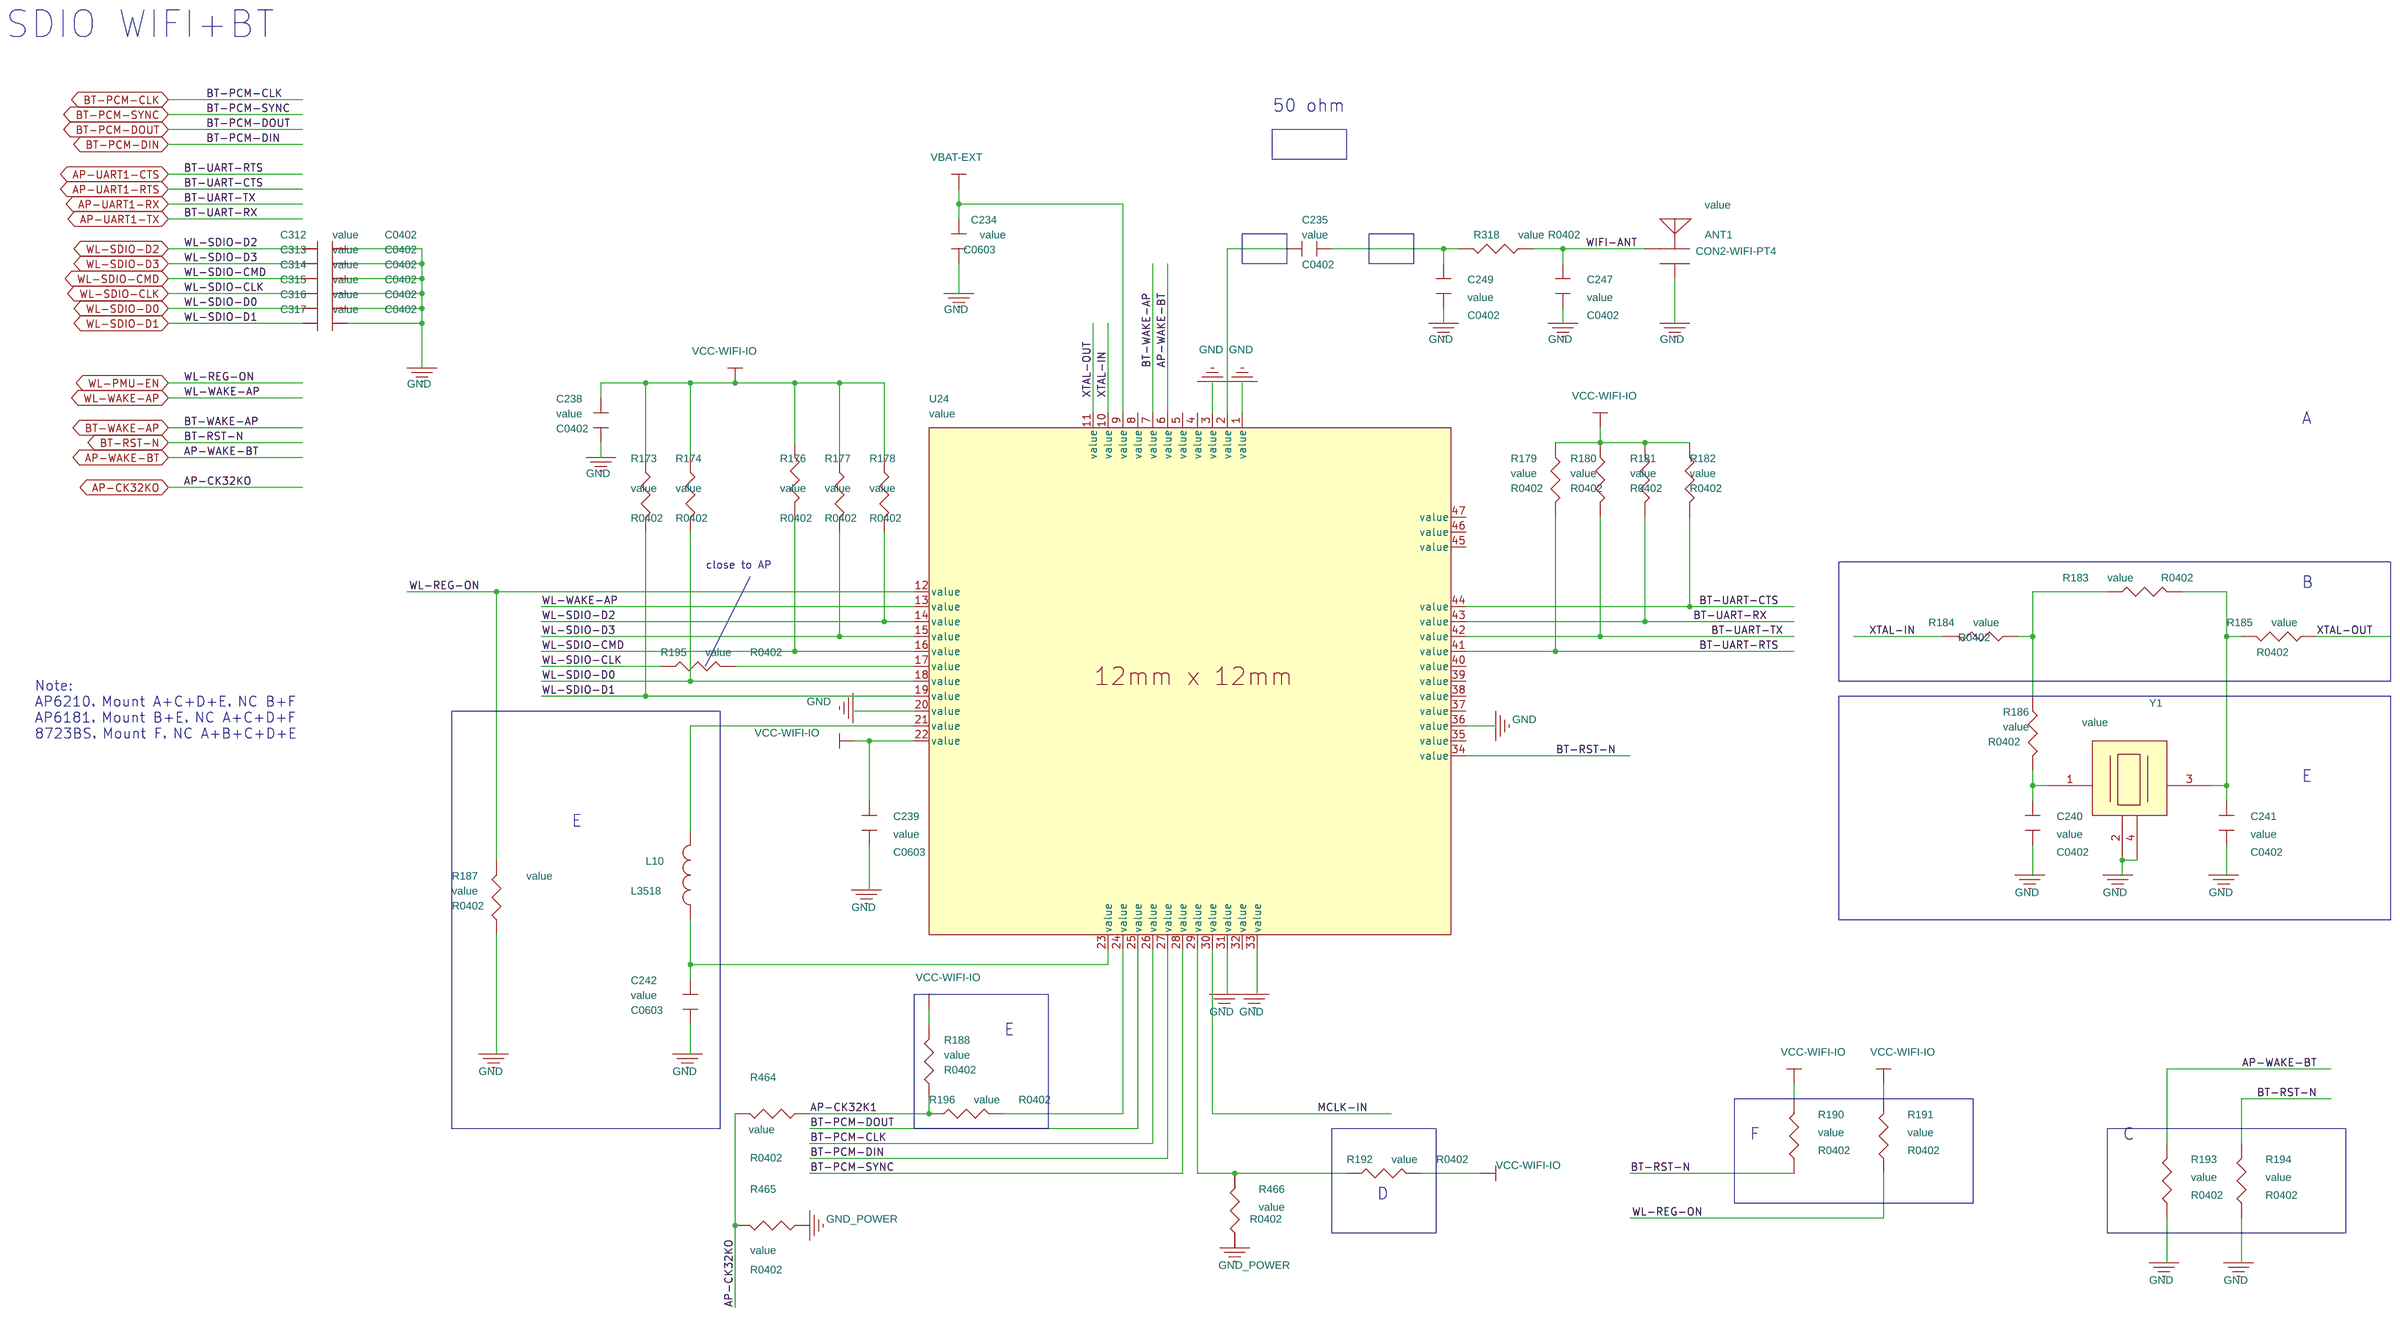
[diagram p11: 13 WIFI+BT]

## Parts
sheet 05 LPDDR3_32X1
DC1  value  [C0402]
DC2  value  [C0603]
DC3  value  [C0402]
DC4  value  [C0402]
DC5  value  [C0402]
DC6  value  [C0402]
DC7  value  [C0402]
DC8  value  [C0402]
DC9  value  [C0402]
DC10  value  [C0402]
DC11  value  [C0402]
DC12  value  [C0603]
DC13  value  [C0402]
DC14  value  [C0402]
DC15  value  [C0402]
DC16  value  [C0402]
DC17  value  [C0402]
DC20  value  [C0402]
DC21  value  [C0402]
DC22  value  [C0402]
DC23  value  [C0402]
DR1  value  [R0402]
DR2  value  [R0402]
DR3  value  [R0402]
DR4  value  [R0402]
DR5  value  [R0402]
DR7  value  [R0402]
DU1  value  [BGA178P0_8X0_65B13X11_5H1_13]  (sections A,B)
U1  value  [BGA345P0_65B14X14]  (sections A,B,C,D)
sheet 06 CPU
C3  value  [C0402]
C4  value  [C0402]
C5  value  [C0402]
C6  value  [C0603]
C7  value  [C0402]
C8  value  [C0402]
C11  value  [C0402]
C12  value  [C0402]
C13  value  [C0402]
C14  value  [C0402]
C15  value  [C0402]
C17  value  [C0402]
C18  value  [C0402]
C19  value  [C0402]
C20  value  [C0402]
C21  value  [C0402]
C22  value  [C0402]
C23  value  [C0603]
C24  value  [C0402]
C25  value  [C0402]
C26  value  [C0402]
C27  value  [C0402]
C28  value  [C0402]
C29  value  [C0402]
C30  value  [C0402]
C31  value  [C0402]
C33  value  [C0402]
C34  value  [C0402]
C35  value  [C0402]
C36  value  [C0402]
C37  value  [C0603]
C38  value  [C0402]
C39  value  [C0402]
C41  value  [C0402]
C42  value  [C0402]
C43  value  [C0603]
C44  value  [C0402]
C45  value  [C0402]
C46  value  [C0402]
C47  value  [C0402]
C277  value  [C0402]
C280  value  [C0402]
R5  value  [R0402]
R6  value  [R0402]
R7  value  [R0402]
R8  value  [R0402]
R28  value  [R0402]
R125  value  [R0402]
R497  value  [R0402]
R498  value  [R0402]
X1  value  [CRY-TSX3225]
sheet 07 POWER
C50  value  [C0603]
C53  value  [C0603]
C56  value  [C0603]
C57  value  [C0603]
C59  value  [C0603]
C61  value  [C0603]
C63  value  [C0603]
C64  value  [C0603]
C65  value  [C0603]
C66  value  [C0603]
C67  value  [C0402]
C68  value  [C0603]
C69  value  [C0603]
C70  value  [C0603]
C71  value  [C0603]
C72  value  [C0603]
C74  value  [C0603]
C75  value  [C0603]
C76  value  [C0603]
C77  value  [C0603]
C78  value  [C0603]
C79  value  [C0402]
C81  value  [C0603]
C82  value  [C0603]
C83  value  [C0603]
C88  value  [C0603]
C89  value  [C0603]
C90  value  [C0603]
C91  value  [C0603]
C92  value  [C0402]
C93  value  [C0603]
C94  value  [C0603]
C263  value  [C0603]
C264  value  [C0402]
C265  value  [C0805]
C266  value  [C0805]
C267  value  [C0603]
C268  value  [C0603]
C269  value  [C0603]
C270  value  [C0603]
C271  value  [C0603]
C272  value  [C0603]
C273  value  [C0603]
C275  value  [C0603]
C276  value  [C0603]
C278  value  [C0603]
C279  value  [C0603]
D1  value  [LED0805]
D2  value  [C0402]
D3  value  [LED0805]
L1  value  [L4018]
L2  value  [L4018]
L3  value  [L4018]
L5  value  [L4018]
L6  value  [L4018]
L7  value  [L4018]
L11  value  [CD32]
OD1  value  [SOD123]
OL1  value  [CD43]
OU1  value  [SOT23-6]
Q4  value  [DFN8P0_65B2_00X2_00H0_75]
R11  value  [R0402]
R12  value  [R0402]
R14  value  [R0402]
R17  value  [R0402]
R18  value  [R0402]
R19  value  [R0402]
R22  value  [R0402]
R23  value  [R0402]
R319  value  [R0805]
R328  value  [R0402]
R329  value  [R0402]
R463  value  [R0805]
SW9  value  [SW4_SMD]
TP61  value  [TP_SMD]
TP62  value  [TP_SMD]
TP70  value  [TP_SMD]
TP71  value  [TP_SMD]
sheet 08 NAND-eMMC
C95  value  [C0402]
C96  value  [C0402]
C98  value  [C0402]
C99  value  [C0402]
C100  value  [C0402]
C101  value  [C0402]
R24  value  [R0402]
R25  value  [R0402]
R26  value  [R0402]
R27  value  [R0402]
R29  value  [R0402]
R325  value  [R0402]
R326  value  [R0402]
U29  value  [BGA169P0_50B12_00X16_00H1_00]  (sections A,B)
sheet 09 CAMERA
C199  value  [C0603]
C204  value  [C0402]
C205  value  [C0603]
C4500  value  [C0603]
C4504  value  [C0603]
C4505  value  [C0603]
C4506  value  [C0402]
C4509  value  [C0402]
C4510  value  [C0603]
C4700  value  [C0402]
C4701  value  [C0402]
C4702  value  [C0603]
C4703  value  [C0603]
C4704  value  [C0402]
C4705  value  [C0402]
J4700  value  [AYF333135]
R4500  value  [R0402]
R4700  value  [R0402]
R4701  value  [R0402]
R4702  value  [R0402]
R4703  value  [R0402]
R4704  value  [R0402]
R4705  value  [R0402]
R4706  value  [R0402]
R4707  value  [R0402]
R4708  value  [R0402]
R5117  value  [R0402]
R5118  value  [R0402]
U14  value  [SOT23_5H14A]
U4500  value  [SOT23_5H14A]
U4502  value  [SOT23_5H14A]
sheet 10 MIPI DSI
C16  value  [C0603]
C48  value  [C0603]
C51  value  [C0603]
C117  value  [C0603]
C119  value  [C0402]
C130  value  [C0603]
C131  value  [C0402]
C132  value  [C0805]
C133  value  [C0402]
C134  value  [C0402]
C135  value  [C0603]
C136  value  [C0402]
C216  value  [C0603]
C217  value  [C0402]
C218  value  [C0603]
C222  value  [C0402]
C236  value  [C0402]
C261  value  [C0402]
C4717  value  [C0402]
D5  value  [SOD123]
D6  value  [SOD123]
D12  value  [SOD123]
D13  value  [SOD123]
L4  value  [CD32]
L9  value  [L4018]
OLED1  value  [CON39-PT0_6H1_8B]
Q7  value  [SOT-23]
Q8  value  [SOT-23]
R9  value  [0805]
R10  value  [0805]
R75  value  [R0402]
R85  value  [R0402]
R86  value  [R0402]
R87  value  [R0603]
R88  value  [R0402]
R89  value  [R0402]
R90  value  [R0402]
R91  value  [R0402]
R92  value  [R0402]
R93  value  [R0402]
R127  value  [R0402]
R138  value  [R0402]
R504  value  [R0402]
R505  value  [R0402]
R1003  value  [R0603]
R1008  value  [R0402]
R1009  value  [R0402]
T35  value  [TP40_SMD]
TP41  value  [TP_SMD]
TP42  value  [TP_SMD]
TP43  value  [TP_SMD]
TP44  value  [TP_SMD]
U6  value  [sot23-5]
U11  value  [SOT23-6]
U15  value  [SOT23_5H14A]
sheet 11 CARD-SENSOR-VIBRATOR-KEY-OTG
C176  value  [C0603]
C182  value  [C0402]
C183  value  [C0402]
C184  value  [C0603]
C326  value  [C0402]
D14  value  [C0402]
D15  value  [C0402]
D16  value  [C0402]
D17  value  [C0402]
D18  value  [C0402]
D19  value  [C0402]
D20  value  [C0402]
D21  value  [C0402]
D30  value  [C0402]
D31  value  [C0402]
D36  value  [C0402]
D37  value  [C0402]
D38  value  [C0402]
D39  value  [LED0603]
D40  value  [LED0603]
ED25  value  [R0402]
ED26  value  [R0402]
ED27  value  [R0402]
J3  value  [FPC4-PT1_25-3_8X10H4_6B]
J8  value  [MICROSD_SLOT]
Q17  value  [SOT-23]
Q18  value  [SOT-23]
R121  value  [R0603]
R122  value  [R0402]
R123  value  [R0402]
R132  value  [R0402]
R133  value  [R0402]
R134  value  [R0402]
R135  value  [R0402]
R136  value  [R0402]
R137  value  [R0402]
R139  value  [R0402]
R140  value  [R0402]
R475  value  [R0402]
R476  value  [R0402]
R477  value  [R0402]
R478  value  [R0402]
R479  value  [R0402]
R480  value  [R0402]
R1010  value  [R0402]
R5124  value  [R0402]
SW8  value  [SW4_SMD]
TP47  value  [TP_SMD]
TP67  value  [TP_SMD]
U19  value  [SOT23-5]
USB1  value  [MIRCO_USB-5PH3A_DIP]
sheet 12 CODEC
C187  value  [C0603]
C188  value  [C0402]
C190  value  [C0603]
C194  value  [C0402]
C196  value  [C0402]
C197  value  [C0402]
C198  value  [C0402]
C200  value  [C0402]
C201  value  [C0402]
C202  value  [C0603]
C206  value  [C0603]
C208  value  [C0402]
C209  value  [C0402]
C211  value  [C0402]
C212  value  [C0603]
C226  value  [C0402]
C227  value  [C0402]
C228  value  [C0402]
C229  value  [C0402]
C230  value  [C0402]
C232  value  [C0402]
C233  value  [C0402]
C327  value  [C0402]
C328  value  [C0402]
C329  value  [C0402]
C330  value  [C0402]
C331  value  [C0402]
C332  value  [C0805]
C333  value  [C0402]
D26  value  [C0402]
D27  value  [C0402]
D28  value  [C0402]
D29  value  [C0402]
ED1  value  [E0402N]
ED2  value  [E0402N]
FB1  value  [L0402]
FB2  value  [L0402]
FB3  value  [L0603]
J4702  value  [PJ342]
R33  value  [R0402]
R144  value  [R0402]
R149  value  [R0402]
R150  value  [R0402]
R151  value  [R0402]
R152  value  [R0402]
R162  value  [R0402]
R169  value  [R0402]
R473  value  [R0402]
R474  value  [R0402]
R506  value  [R0402]
R507  value  [R0402]
R5119  value  [R0402]
R5120  value  [R0402]
R5121  value  [R0402]
R5122  value  [R0402]
R5123  value  [R0402]
TP50  value  [TP_SMD]
TP51  value  [TP_SMD]
TP52  value  [TP_SMD]
TP53  value  [TP_SMD]
TP54  value  [TP_SMD]
TP68  value  [TP_SMD]
TP69  value  [TP_SMD]
U28  value  [BGA218_P0_65B11X11]  (sections A,B,C,D)
U103  value  [MSOP8-PT1-27A]
X2  value  [XCOL-SMD]
sheet 13 WIFI+BT
ANT1  value  [CON2-WIFI-PT4]
C234  value  [C0603]
C235  value  [C0402]
C238  value  [C0402]
C239  value  [C0603]
C240  value  [C0402]
C241  value  [C0402]
C242  value  [C0603]
C247  value  [C0402]
C249  value  [C0402]
C312  value  [C0402]
C313  value  [C0402]
C314  value  [C0402]
C315  value  [C0402]
C316  value  [C0402]
C317  value  [C0402]
L10  value  [L3518]
R173  value  [R0402]
R174  value  [R0402]
R176  value  [R0402]
R177  value  [R0402]
R178  value  [R0402]
R179  value  [R0402]
R180  value  [R0402]
R181  value  [R0402]
R182  value  [R0402]
R183  value  [R0402]
R184  value  [R0402]
R185  value  [R0402]
R186  value  [R0402]
R187  value  [R0402]
R188  value  [R0402]
R190  value  [R0402]
R191  value  [R0402]
R192  value  [R0402]
R193  value  [R0402]
R194  value  [R0402]
R195  value  [R0402]
R196  value  [R0402]
R318  value  [R0402]
R464  value  [R0402]
R465  value  [R0402]
R466  value  [R0402]
U24  value  [QFN44P0_90B12_00X12_00H1_50]
Y1  value  [CRY-TSX3225]
sheet 14 TP
C281  value  [C0402]
C282  value  [C0603]
C341  value  [C0603]
ED28  value  [R0402]
ED29  value  [R0402]
ED30  value  [R0402]
ED32  value  [R0402]
ED33  value  [R0402]
ED34  value  [R0402]
J9  value  [FPC8-PT0.5-H1_9A]
R129  value  [R0402]
R1006  value  [R0402]
R1007  value  [R0402]
TP74  value  [TP_SMD]
U1000  value  [SOT23-6]
sheet 15 SENSOR
C179  value  [C0402]
C180  value  [C0402]
C185  value  [C0402]
C186  value  [C0402]
C189  value  [C0402]
C191  value  [C0402]
C203  value  [C0402]
C289  value  [C0402]
C290  value  [C0402]
C291  value  [C0402]
C292  value  [C0402]
C4718  value  [C0402]
C4719  value  [C0402]
R126  value  [R0402]
R128  value  [R0402]
R167  value  [R0402]
R168  value  [R0402]
R481  value  [R0402]
R482  value  [R0402]
R483  value  [R0402]
R484  value  [R0402]
R485  value  [R0402]
R486  value  [R0402]
R487  value  [R0402]
R488  value  [R0402]
R489  value  [R0402]
R490  value  [R0402]
R491  value  [R0402]
R517  value  [R0402]
R518  value  [R0402]
R519  value  [R0402]
R520  value  [R0402]
R521  value  [R0402]
R522  value  [R0402]
R5132  value  [R0402]
R5133  value  [R0402]
R5134  value  [R0402]
R5135  value  [R0402]
R5136  value  [R0402]
TST  value  [TP_SMD]
U30  value  [QFN24-3X3]
U100  value  [BGA156]
U101  value  [BGA160]
U4503  value  [AK09911]
U4505  value  [BMI160]

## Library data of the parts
C50 C53 C56 C57 C59 C61 C63-C66 C68-C72 C74-C78 C81-C83 C88-C94 C197 C202 C206 C208 C212 C263-C273 C275 C276 C278 C279 DC1 DC7-DC17 DC20-DC23 = CAPACITOR_0: PAGE: 1
C11 C28 C31 C42 C117 C119 C130-C136 C176 C179 C180 C185-C187 C189 C191 C203 C232-C235 C238-C242 C247 C249 C277 C280 C312-C317 DC2-DC6 = CAPACITOR_0: PAGE: 2
DR1 DR3 DR7 = ?_0
DR2 DR4 R132-R135 R149-R151 = R1_0805
DR5 R5-R8 R11 R12 R14 R17-R19 R22 R23 R33 R121-R123 R125 R126 R128 R136 R137 R139 R140 R144 R152 R162 R169 R173 R174 R176-R188 R190-R196 R318 R319 R328 R329 R463-R466 R473-R491 R497 R498 R517-R522 R1006 R1007 R1010 R5124 R5132-R5136 = R
DU1 = LPDDR3_FBGA178_0
U1 = A83_0
C3 C4 = CAPACITOR_0: PAGE: 2; mypage: 09
C5-C8 C12-C15 C17-C27 C29 C30 C33-C39 C41 C43-C47 C67 C79 C188 C209 C211 C226-C230 = CAPACITOR_0
R24-R29 R325 R326 = R: mypage: 08
X1 = CRYSTAL-4_2: Crystal 24MHz 20pF 10ppm  -30 to +85; PART NUMBER: 7M24000004; SPREADWIN PN: U3000019A; Vendor: TXC
D1 D3 D39 D40 = LED_0: PAGE: 1
D2 D14-D21 D26-D31 D36-D38 = 1_1.5KE100A: 1ST PART DESCRIPTION: WILL ESD9B5V Bidirection ESD Protection
L1-L3 L5-L7 L11 OL1 = INDUCTOR_0
OD1 = DIODE_SCHOTTKY
OU1 = RT9266PE_0
Q4 = WPM4005_11
SW8 SW9 = SW_PUSH
TP41-TP44 TP47 TP50-TP54 TP61 TP62 TP67-TP71 TP74 TST = T_POINT_R
C95 C96 C98-C101 = CAPACITOR_0: PAGE: 2; mypage: 08
U29 = EMMC5_0_BGA169_0
C199 C205 C216 C218 C4500 = SMALL_CAP: 贴片电容
C204 C217 C222 C236 C261 C282 C341 C4505 C4506 C4509 C4510 C4717 = CAP_NP
C281 C289 C4504 C4705 = CAP_NP: CAP,MLCC,100nF,+/-10%,X7R,6.3V,SMD0402
C4700 C4701 = CAP_NP: CAP,MLCC,8pF,+/-10%,NPO,6.3V,SMD0402
C4702-C4704 = CAP_NP: CAP,MLCC,1uF,+/-10%,X5R,6.3V,SMD0402
J4700 = LCM0200CE1A0_2: Camera Conncetor, 24pin,SMT
R4500 = RES_1B
R4700 R4701 R4705-R4708 R5117 R5118 = RESISTOR_0
R4702 R4703 = RESISTOR_0: RES,thick film,22Ohm,+/-5%,1/16W,SMD0402
R4704 = RESISTOR: NC
U14 U15 U4500 U4502 = LDO-PT5108_RT9013_0
C16 = CAP_P_1210
C48 C51 = CAPACITOR_3: PAGE: 3
D5 D6 D13 = DIODE_SCHOTTKY_0: PAGE: 3
D12 = D_0: Allegro PCB Footprint: d2513A
L4 = INDUCTOR: PAGE: 3
L9 = INDUCTOR: RoHS Power Inductor 22uH 300mA H<1.8MM,CD32
OLED1 = 40P_MIPI_0
Q7 Q8 Q17 Q18 = NPN
R9 R10 = RESISTOR_3: PAGE: 3
R75 R85-R93 R504 R505 R1003 R1008 R1009 = RESISTOR
R127 R138 = RES_1B: ROHS CHIP RES 4.7K 1/16W 5%
T35 = TESTPOINT1: TEST
U6 = SP6646_0: PAGE: 3
U11 = AP3031_0
C182-C184 C326 = CAPACITOR
ED25-ED30 ED32-ED34 = DIODE_BI-DIR_TRIG: ESD
J3 = CON2_2
J8 = SDMMC_SLOT_0
U19 = RT9266PE_2
USB1 = USB_MINI_SOCKET_5: USB JACK ROHS
C190 C194 C196 C198 C200 C201 = CAPACITOR: PAGE: 2
C327 = CAP_NP: RoHS CHIP CAP 1uF +10/-10% X5R; BOM_TYPE: 30; BOM_VALUE: 0
C328-C331 C333 = CAP_NP: RoHS CHIP CAP 0.1uF +10/-10% X7R; BOM_TYPE: 30; BOM_VALUE: 0
C332 = CAP_NP: RoHS CHIP CAP 10uF +10/-10% X5R; BOM_TYPE: 30; BOM_VALUE: 0; MARK: 106; ROOM: USB+5V
ED1 ED2 = DIODE_BI-DIR_TRIG: NC/ESD Component,5V,30P,SMD,0402; BOM_TYPE: 43; BOM_VALUE: 0
FB1 FB2 = INDUCTOR_2
FB3 = INDUCTOR: ROHS CHIP RES 0 Ohm 1/16W +/-5%; BOM_TYPE: 20; BOM_VALUE: 0; Supplier: MURATA; Supplier P/N: BLM18PG181SN1D
J4702 = HP_JACK_0
R506 = RESISTOR: ROHS CHIP RES 30K 1/16W +/-5%; BOM_TYPE: 20; BOM_VALUE: 0
R507 R5121 R5122 = RESISTOR: ROHS CHIP RES 62K 1/16W +/-5%; BOM_TYPE: 20; BOM_VALUE: 0
R5119 = RESISTOR: ROHS CHIP RES 1M 1/16W +/-5%; BOM_TYPE: 20; BOM_VALUE: 0
R5120 R5123 = RESISTOR: ROHS CHIP RES 100K 1/16W +/-5%
U28 = AW1660_70_BGA218_1
U103 = LM4990_0: Class D Audio AMP; BOM_TYPE: 10; BOM_VALUE: 8
X2 = CRYSTAL_XCOL-3
ANT1 = T_POINT_R_0
L10 = INDUCTOR
U24 = AP6493_0: Device: APSERIES; ORCAD_LIB: MODULE; QVL: AMPAK
Y1 = Crystal_0
J9 = touch_screen_1
R129 = RESISTOR: RES,thick film,33Ohm,+/-5%,1/16W,SMD0402
U1000 = LM1086_2
C290 C292 = CAP_NP: CAP,MLCC,1uF,+/-10%,X5R,6.3V,SMD0402; ROOM: CHG
C291 C4718 C4719 = CAP_NP: RoHS CHIP CAP 0.1uF +10/-10% X7R
R167 = RESISTOR_0: NC
R168 = RESISTOR_0: RES,thick film,0Ohm,+/-5%,1/16W,SMD0402
U30 = Sensor_MPU6500_0
U100 = BMC156_0
U101 = BMG160_1
U4503 = AK09911_0
U4505 = BMG160_0

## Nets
AVDD-CSI: C275.1 U28.E10(value)
DVDD-CSI-F: C271.1 U28.E16(value)
GND: ANT1.2 C3.2 C4.2 C5.1 C6.1 C7.2 C8.2 C11.1 C12.1 C13.2 C14.1 C15.2 C16.1 C17.1 C18.1 C19.1 C20.1 C21.1 C22.1 C23.1 C24.1 C25.1 C26.1 C27.1 C28.1 C29.1 C30.1 C31.1 C33.1 C34.1 C35.1 C36.1 C37.1 C38.1 C39.1 C41.1 C42.1 C43.1 C44.1 C45.1 C46.1 C47.1 C48.2 C50.2 C53.1 C56.2 C57.2 C59.2 C61.2 C63.2 C64.2 C65.1 C66.2 C67.2 C68.2 C69.1 C70.1 C71.1 C72.2 C74.1 C75.2 C76.1 C77.2 C78.1 C79.1 C81.1 C82.2 C83.2 C88.1 C89.1 C90.1 C91.1 C92.1 C93.1 C94.1 C95.1 C96.1 C98.1 C99.1 C100.1 C101.1 C117.1 C119.1 C130.1 C131.1 C132.1 C133.1 C134.1 C135.1 C136.1 C176.1 C179.1 C180.1 C182.1 C183.1 C184.1 C185.1 C186.1 C187.1 C188.1 C189.1 C190.1 C191.1 C197.2 C199.2 C200.1 C201.1 C202.2 C203.1 C204.2 C205.2 C216.2 C217.2 C218.2 C222.2 C226.1 C227.1 C228.1 C229.1 C230.1 C232.1 C233.1 C234.1 C236.2 C238.1 C239.2 C240.2 C241.2 C242.2 C247.2 C249.2 C261.2 C263.1 C265.1 C266.1 C267.1 C268.1 C269.1 C270.1 C271.2 C272.2 C273.2 C275.2 C276.1 C277.2 C278.2 C279.2 C280.1 C281.2 C282.2 C289.2 C290.1 C291.1 C292.2 C312.1 C313.1 C314.1 C315.1 C316.1 C317.1 C326.1 C327.1 C329.2 C331.2 C332.2 C333.2 C341.2 C4500.2 C4504.2 C4505.2 C4506.2 C4509.2 C4510.1 C4700.1 C4701.1 C4702.2 C4703.2 C4704.1 C4705.1 C4717.2 C4718.1 C4719.1 D2.2(CATHODE) D3.2(CATHODE) D13.2 D14.2(CATHODE) D15.2(CATHODE) D16.2(CATHODE) D17.2(CATHODE) D18.2(CATHODE) D19.2(CATHODE) D20.2(CATHODE) D21.2(CATHODE) D26.2(CATHODE) D27.2(CATHODE) D28.2(CATHODE) D29.2(CATHODE) D30.2(CATHODE) D31.2(CATHODE) D36.2(CATHODE) D37.2(CATHODE) D38.2(CATHODE) DC1.1 DC2.1 DC3.1 DC4.1 DC5.1 DC6.1 DC7.1 DC9.1 DC10.1 DC11.1 DC12.1 DC13.1 DC14.1 DC15.1 DC16.1 DC17.1 DC20.1 DC21.1 DC22.1 DC23.1 DR2.1 DR4.1 DR5.2 DR7.1 DU1.B2(value) DU1.B5(value) DU1.B6(value) DU1.B12(value) DU1.C3(value) DU1.C5(value) DU1.C6(value) DU1.D3(value) DU1.D12(value) DU1.E4(value) DU1.E5(value) DU1.E6(value) DU1.F4(value) DU1.F5(value) DU1.F6(value) DU1.F12(value) DU1.G3(value) DU1.G4(value) DU1.G6(value) DU1.G9(value) DU1.H2(value) DU1.H10(value) DU1.J4(value) DU1.J12(value) DU1.K2(value) DU1.K10(value) DU1.L6(value) DU1.L9(value) DU1.M4(value) DU1.M5(value) DU1.M6(value) DU1.M12(value) DU1.N4(value) DU1.N5(value) DU1.N6(value) DU1.P3(value) DU1.P12(value) DU1.R4(value) DU1.R5(value) DU1.R6(value) DU1.T2(value) DU1.T3(value) DU1.T4(value) DU1.T5(value) DU1.T6(value) DU1.T12(value) ED1.2 ED2.2 ED25.2 ED26.2 ED27.2 ED28.2 ED29.2 ED30.2 ED32.2 ED33.2 ED34.2 J3.3 J3.5 J3.6 J8.6(value) J8.10(value) J9.7 J9.8 J4700.1(value) J4700.3(value) J4700.16(value) J4700.25(value) J4700.29(value) J4700.31(value) OLED1.1(value) OLED1.7(value) OLED1.11(value) OLED1.15(value) OLED1.19(value) OLED1.23(value) OLED1.27(value) OLED1.31(value) OLED1.36(value) OLED1.40 OLED1.41 OU1.2(value) Q7.2(E) Q8.2(E) Q17.2(E) Q18.2(E) R8.2 R9.2 R14.2 R19.2 R23.2 R75.2 R87.2 R91.1 R137.1 R139.1 R149.1 R150.1 R151.1 R152.1 R168.1 R187.1 R193.1 R194.1 R325.1 R326.1 R465.1 R466.1 R478.1 R480.2 R484.1 R491.2 R1003.2 R1008.2 R1009.2 R4500.2 R4708.1 R5119.2 SW8.2 SW8.3 SW8.4(6) SW9.2 SW9.3 SW9.4(6) TP62.1(TP) TP71.1(TP) U1.A1(value) U1.A21(value) U1.AA1(value) U1.AA21(value) U1.C7(value) U1.C11(value) U1.F5(value) U1.G6(value) U1.G16(value) U1.G17(value) U1.H6(value) U1.H8(value) U1.H12(value) U1.H14(value) U1.H16(value) U1.J8(value) U1.J13(value) U1.J17(value) U1.K5(value) U1.K8(value) U1.K9(value) U1.K10(value) U1.K11(value) U1.K12(value) U1.L8(value) U1.L16(value) U1.M8(value) U1.N5(value) U1.N9(value) U1.N10(value) U1.N11(value) U1.N12(value) U1.N14(value) U1.N17(value) U1.P8(value) U1.P12(value) U1.P16(value) U1.T14(value) U1.T18(value) U1.U6(value) U6.2(value) U11.2(value) U14.2(value) U15.2(value) U19.2(GND) U24.1(value) U24.3(value) U24.20(value) U24.31(value) U24.33(value) U24.36(value) U28.D4(value) U28.D5(value) U28.D6(value) U28.D7(value) U28.E4(value) U28.E5(value) U28.E7(value) U28.F3(value) U28.F4(value) U28.F5(value) U28.F6(value) U28.G3(value) U28.G4(value) U28.G5(value) U28.G6(value) U28.G7(value) U28.G8(value) U28.G9(value) U28.G10(value) U28.G11(value) U28.G12(value) U28.G13(value) U28.G14(value) U28.H3(value) U28.H4(value) U28.H5(value) U28.H6(value) U28.H7(value) U28.H8(value) U28.H9(value) U28.H10(value) U28.H11(value) U28.H12(value) U28.H13(value) U28.H14(value) U28.J7(value) U28.J8(value) U28.J9(value) U28.J10(value) U28.J11(value) U28.J12(value) U28.J13(value) U28.J14(value) U28.K7(value) U28.K8(value) U28.K9(value) U28.K10(value) U28.K11(value) U28.K12(value) U28.K13(value) U28.K14(value) U28.L7(value) U28.L8(value) U28.L9(value) U28.L10(value) U28.L11(value) U28.L12(value) U28.L13(value) U28.L14(value) U28.M7(value) U28.M8(value) U28.M9(value) U28.M10(value) U28.M11(value) U28.M12(value) U28.M13(value) U28.M14(value) U28.N7(value) U28.N8(value) U28.N9(value) U28.N10(value) U28.N11(value) U28.N12(value) U28.N13(value) U28.N14(value) U28.P4(value) U28.P5(value) U28.P7(value) U28.P8(value) U28.P9(value) U28.P10(value) U28.P11(value) U28.P12(value) U28.P13(value) U28.P14(value) U29.AA4(value) U29.AA6(value) U29.K4(value) U29.M7(value) U29.P5(value) U29.R10(value) U29.U8(value) U29.Y2(value) U29.Y5(value) U30.11(value) U30.18(value) U30.20(value) U100.4(value) U100.8(value) U100.9(value) U101.3(value) U101.8(value) U101.11(value) U103.7(value) U1000.2(value) U4500.2(value) U4502.2(value) U4503.B1(value) U4505.1(value) U4505.6(value) U4505.7(value) USB1.5(value) USB1.6(value) USB1.7(value) USB1.8(value) USB1.9(value) X1.2(value) X1.4(value) X2.3(Shield) Y1.2 Y1.4
VBAT: C264.2 C267.2 R319.1 TP70.1(TP) U28.L15(value)
VCC15_DVP: C4510.2 R4706.1 U4502.5(value)
VCC18_DVP: C205.1 C4703.1 J4700.12(value) R4700.1 R4701.1 R4704.2 R4705.1 U14.5(value)
VCC28_DVP: C4504.1 C4702.1 J4700.5(value) U4500.5(value)
VCC-DRAM: C65.2 C88.2 DC2.2 DC3.2 DC4.2 DC5.2 DC6.2 DC8.2 DC10.2 DC11.2 DC12.2 DC13.2 DC14.2 DC15.2 DC16.2 DC17.2 DR1.2 DU1.A8(value) DU1.A9(value) DU1.A11(value) DU1.C12(value) DU1.D4(value) DU1.D5(value) DU1.D6(value) DU1.E8(value) DU1.E12(value) DU1.F2(value) DU1.G2(value) DU1.G5(value) DU1.G12(value) DU1.H3(value) DU1.H5(value) DU1.H6(value) DU1.H8(value) DU1.H9(value) DU1.H11(value) DU1.H12(value) DU1.J5(value) DU1.J6(value) DU1.J9(value) DU1.J10(value) DU1.K5(value) DU1.K6(value) DU1.K8(value) DU1.K11(value) DU1.K12(value) DU1.L2(value) DU1.L5(value) DU1.L12(value) DU1.M2(value) DU1.N8(value) DU1.N12(value) DU1.P4(value) DU1.P5(value) DU1.P6(value) DU1.R12(value) DU1.U8(value) DU1.U9(value) DU1.U11(value) L6.2 U1.E7(value) U1.F7(value) U1.J6(value) U1.K6(value) U1.L6(value) U1.M6(value) U1.N6(value) U1.P6(value) U1.R6(value) U28.F12(value) U28.F15(value)
VCC-PD: C4.1 R328.1 R329.1 U1.F13(value) U1.F14(value)
VCC-RTC: C3.1 C19.2 C20.2 C70.2 C226.2 R33.1 R473.1 R474.1 U1.F8(value) U1.F12(value) U1.L14(value) U1.T8(value) U28.D8(value) U28.T14(value)
VCC_TP: C281.1 C282.1 J9.3 R129.2
VDD-CORE: C187.2 C188.2 U28.A9(value)
VDD-CPUA: C37.2 C38.2 C39.2 C41.2 C56.1 L2.2 U1.L9(value) U1.L10(value) U1.L11(value) U1.L12(value) U1.M9(value) U1.M11(value) U1.M12(value) U1.M13(value) U1.M14(value)
VDD-CPUB: C43.2 C44.2 C45.2 C46.2 C47.2 C59.1 L3.2 U1.F10(value) U1.F11(value) U1.H9(value) U1.H10(value) U1.H11(value) U1.J9(value) U1.J10(value) U1.J11(value)
VDD-GPU: C23.2 C24.2 C25.2 C26.2 C27.2 C63.1 L5.2 U1.P9(value) U1.P10(value) U1.P11(value) U1.T11(value) U28.N4(value)
VDDFB-CPUA: U1.M10(value) U28.T11(value)
VDDFB-CPUB: U1.J12(value) U28.R11(value)
VDDIO: C4719.2 R5136.2 U4505.5(value) U4505.12(value)
AD0: R167.1 R168.2 U30.9(value)
ALDO1: C13.1 C29.2 C30.2 C74.2 R328.2 U1.H13(value) U1.K14(value) U1.N13(value) U1.U13(value) U28.R6(value)
ALDO2: C5.2 C6.2 C7.1 C76.2 C197.1 C230.2 DC1.2 DC22.2 DC23.2 DU1.A3(value) DU1.A4(value) DU1.A5(value) DU1.A6(value) DU1.A10(value) DU1.U3(value) DU1.U4(value) DU1.U5(value) DU1.U6(value) DU1.U10(value) U1.N8(value) U1.T12(value) U1.T13(value) U28.H2(value) U28.T4(value)
ALDO3: C11.2 C78.2 C227.2 R162.2 U1.T15(value) U28.C2(value) U28.T5(value)
AP-CK32K1: R188.1 R196.1 R464.1
AP-CK32KO: R464.2 R465.2 U28.C7(value)
AP-CSI-SCK: J4700.6(value) R4700.2 U1.C12(value)
AP-CSI-SDA: J4700.4(value) R4701.2 U1.B13(value)
AP-I2S-BCLK: U1.A10(value) U28.R2(value)
AP-I2S-DIN: U1.B9(value) U28.P2(value)
AP-I2S-DOUT0: U1.E9(value) U28.P1(value)
AP-I2S-LRCK: U1.C9(value) U28.R1(value)
AP-I2S-MCLK: U1.C8(value) U28.T2(value)
AP-NMI#: C280.2 R33.2 U1.Y16(value) U28.A11(value)
AP-RESET#: C79.2 C277.1 R17.2 R93.1 R1006.1 U1.AA16(value)
AP-UART1-CTS: R179.2 U1.N19(value) U24.41(value)
AP-UART1-RTS: R182.2 U1.N18(value) U24.44(value)
AP-UART1-RX: R180.2 U1.N16(value) U24.42(value)
AP-UART1-TX: R181.2 U1.M19(value) U24.43(value)
AP-WAKE-BT: R193.2 U1.W7(value) U24.6(value)
AS-INT: R482.2 U1.P19(value) U30.12(value)
AUX_CL: R521.1 U30.7(value)
AUX_DA: R522.1 U30.21(value)
BACK: R135.2 TP74.1(TP)
BB-VBAT: C234.2 C264.1 C268.2 C269.2 L11.2 Q4.1(D1) Q4.2(D2) Q4.5(D3) Q4.6(D4) Q4.8(D5) R319.2 U24.9(value) U28.L16(value)
BMG160-SCK: R518.2 R520.2 R521.2 R5134.1 U101.7(value) U4503.B3(value)
BMG160SDA: R517.2 R519.2 R522.2 R5135.1 U101.9(value) U4503.C3(value)
BT-PCM-CLK: U24.26(value) U28.K2(value)
BT-PCM-DIN: U24.27(value) U28.K1(value)
BT-PCM-DOUT: U24.25(value) U28.J1(value)
BT-PCM-SYNC: U24.28(value) U28.J3(value)
BT-RST-N: R190.1 R194.2 U24.34(value)
BT-WAKE-AP: U1.W17(value) U24.7(value)
CAD: R490.1 R491.1 U4503.A2(value)
CIF_CLKI: C4700.2 R4702.2 U1.E15(value)
CIF_CLKIN: J4700.18(value) R4702.1
CIF_CLKO: R4703.2 U1.E16(value)
CIF_CLKOUT: C4701.2 J4700.14(value) R4703.1
CIF_D0: J4700.20(value) U1.D15(value)
CIF_D1: J4700.22(value) U1.F15(value)
CIF_D2: J4700.23(value) U1.E13(value)
CIF_D3: J4700.21(value) U1.D13(value)
CIF_D4: J4700.19(value) U1.B14(value)
CIF_D5: J4700.17(value) U1.F17(value)
CIF_D6: J4700.15(value) U1.C14(value)
CIF_D7: J4700.13(value) U1.E12(value)
CIF_DVDD: C4704.2 J4700.11(value) R4705.2 R4706.2
CIF_HREF: J4700.10(value) U1.D16(value)
CIF_PDN0: R5118.1 U1.B12(value)
CIF_PDN1: R4707.2 R4708.2 R5117.1 U1.A12(value)
CIF_RST: C4705.2 J4700.7(value) R4704.1
CIF_VSYNC: J4700.8(value) U1.C15(value)
DC1-SW: C117.2 C119.2 C135.2 C216.1 C273.1 L4.1 R86.2 R127.1 U6.4(value) U6.5(value) U15.1(value) U28.J5(value)
DCDC1: C12.2 C21.2 C22.2 C53.2 C82.1 C98.2 C99.2 C100.2 C101.2 C179.2 C180.2 C185.2 C186.2 C191.2 C199.1 C203.2 C228.2 C272.1 C289.1 C290.2 C291.2 C326.2 C341.1 C4500.1 C4505.1 C4718.2 ED30.1 L1.2 OU1.4(value) R6.2 R7.2 R18.2 R24.1 R27.1 R29.1 R121.1 R122.1 R123.1 R126.1 R128.2 R129.1 R136.2 R167.2 R329.2 R481.2 R485.2 R489.2 R490.2 R497.2 R498.2 R1007.2 R1010.1 R4707.1 R5123.1 R5124.1 R5136.1 U1.F9(value) U1.L13(value) U1.R16(value) U1.T7(value) U14.1(value) U28.F16(value) U28.J6(value) U28.K6(value) U28.N2(value) U29.AA3(value) U29.AA5(value) U29.K6(value) U29.M6(value) U29.N5(value) U29.T10(value) U29.U9(value) U29.W4(value) U29.Y4(value) U30.8(value) U30.13(value) U30.22(value) U100.3(value) U100.7(value) U101.2(value) U101.10(value) U1000.6(value) U4500.1(value) U4502.1(value) U4503.A1(value) U4503.C1(value) U4505.8(value)
DCDC6: C14.2 C15.1 C33.2 C34.2 C35.2 C36.2 C69.2 L7.2 U1.J14(value) U1.J16(value) U1.K13(value) U1.K16(value) U1.P13(value) U28.E12(value)
DCIN: C265.2 R463.1 U28.N15(value) U28.N16(value)
DLDO1: C229.2 C238.2 C239.1 C279.1 R173.1 R174.1 R176.1 R177.1 R178.1 R179.1 R180.1 R181.1 R182.1 R188.2 R190.2 R191.2 R192.2 U24.22(value) U28.F7(value) U28.J2(value)
DLDO2: C75.1 U28.F8(value)
DLDO3: C77.1 U28.F10(value)
DVP_PWR: R4500.1 U1.D12(value) U14.3(value) U4500.3(value) U4502.3(value)
ELDO1: C83.1 U28.G15(value)
ELDO2: C278.1 U28.D16(value)
ENTER: R134.2 R135.1 TP47.1(TP)
FLDO1: C89.2 U1.P14(value) U28.E15(value)
FLDO2: C17.2 C18.2 C90.2 U1.R17(value) U1.T17(value) U28.F14(value)
GPIO0-LDO: C276.2 U28.T8(value)
GPIO1-LDO: C81.2 U28.T7(value)
HBIAS: C190.2 R144.2 U28.C5(value)
HPDI_INT: U1.V18(value)
HPOUTFB: C196.1 C198.2 C200.2 D26.1(ANODE) J4702.3 R149.2 TP53.1(TP) TP54.1(TP) U28.F2(value)
HPOUTL: C211.2 FB1.1 TP51.1(TP) U28.G2(value)
HPOUTR: C209.2 FB2.1 TP52.1(TP) U28.H1(value)
HS-MIC: C194.2 C196.2 C201.2 D28.1(ANODE) J4702.2(G) R144.1 TP50.1(TP)
ID0: OLED1.2(value) R504.2 R1008.1 TP43.1(TP)
ID1: OLED1.3(value) R505.2 R1009.1 TP44.1(TP)
INT1: R487.1 R5132.1
INT2: R486.1 R5133.1 U1.V7(value)
IR-RX: U1.AA18(value)
IRQ-AUDIO: R162.1 U1.AA19(value) U28.L1(value)
LCD-BL-EN: R90.1 R92.2 U1.C18(value)
LCD-CLK: U1.A18(value)
LCD-D2: U1.A20(value)
LCD-D3: U1.B20(value)
LCD-D4: U1.D18(value)
LCD-D5: U1.D19(value)
LCD-D6: U1.B21(value)
LCD-D7: U1.C20(value)
LCD-D10: U1.C21(value)
LCD-D11: U1.D20(value)
LCD-D12: U1.D21(value)
LCD-D13: U1.E19(value)
LCD-D14: U1.E20(value)
LCD-D15: U1.F18(value)
LCD-D18: U1.A15(value)
LCD-D19: U1.B15(value)
LCD-D20: U1.A16(value)
LCD-D21: U1.B16(value)
LCD-D22: U1.B17(value)
LCD-D23: U1.C16(value)
LCD-DE: U1.B18(value)
LCD-HSYNC: U1.A19(value)
LCD-PWM: R86.1 R88.1 U1.C17(value)
LCD-RST: OLED1.4(value) R75.1
LCD-VSYNC: U1.B19(value)
LCD_+V50AP: C48.1 C261.1 C4717.1 D6.2 OLED1.28(value) R10.1
LCD_-V50AP: C16.2 C236.1 D5.1 OLED1.29(value)
LCDC_BL: R138.1
LCDIO: C218.1 C222.1 OLED1.30(value) R504.1 R505.1 U15.5(value)
LIGHT_INT: ED34.1 J9.6 U1.Y6(value)
LRADC0: C42.2 U1.W15(value)
MBIAS: U28.C6(value)
MCLK-IN: U24.30(value)
MENU: R133.2 R134.1 TP67.1(TP)
MIC1N: U28.B5(value)
MIC1P: U28.A5(value)
MIC2N: C198.1 U28.B4(value)
MIC2P: C194.1 U28.A4(value)
MIPI-CSI2-CLKN: U1.T21(value)
MIPI-CSI2-CLKP: U1.T20(value)
MIPI-CSI2-D0N: U1.U19(value)
MIPI-CSI2-D0P: U1.V19(value)
MIPI-CSI2-D1N: U1.T19(value)
MIPI-CSI2-D1P: U1.U20(value)
MIPI-CSI2-D2N: U1.R21(value)
MIPI-CSI2-D2P: U1.R20(value)
MIPI-CSI2-D3N: U1.P20(value)
MIPI-CSI2-D3P: U1.R19(value)
MIPI-DSI-CKN: OLED1.18(value) U1.G18(value)
MIPI-DSI-CKP: OLED1.16(value) U1.G19(value)
MIPI-DSI-D0N: OLED1.26(value) U1.H20(value)
MIPI-DSI-D0P: OLED1.24(value) U1.J19(value)
MIPI-DSI-D1N: OLED1.22(value) U1.G20(value)
MIPI-DSI-D1P: OLED1.20(value) U1.H19(value)
MIPI-DSI-D2N: OLED1.14(value) U1.F21(value)
MIPI-DSI-D2P: OLED1.12(value) U1.G21(value)
MIPI-DSI-D3N: OLED1.10(value) U1.F19(value)
MIPI-DSI-D3P: OLED1.8(value) U1.F20(value)
MS-INT: R483.2 R488.2 U1.N21(value)
NALE: U1.V12(value)
NCE0: U1.Y12(value)
NCE1: U1.W12(value)
NCE2: U1.Y9(value)
NCE3: U1.AA9(value)
NCLE: U1.AA13(value)
NDQ0: U1.T10(value) U29.H3(value)
NDQ1: U1.U10(value) U29.H4(value)
NDQ2: U1.V10(value) U29.H5(value)
NDQ3: U1.W10(value) U29.J2(value)
NDQ4: U1.Y10(value) U29.J3(value)
NDQ5: U1.AA10(value) U29.J4(value)
NDQ6: U1.T9(value) U29.J5(value)
NDQ7: U1.V9(value) U29.J6(value)
NDQS: U1.W9(value) U29.U5(value)
NRB0: R26.2 R27.2 R29.2 U1.W11(value) U29.W5(value)
NRB1: R24.2 R25.1 U1.Y11(value)
NRBX: R25.2 R26.1
NRE: R28.1 U29.W6(value)
NWE: U1.Y13(value)
PA-SHDN: R5120.2 R5123.2 U1.U16(value)
PHONE_DET: R5119.1 R5120.1 U103.1(value)
PMU-SCK: R473.2 U1.AA15(value) U28.B10(value)
PMU-SDA: R474.2 U1.W14(value) U28.C9(value)
PS: C50.1 C57.1 C61.1 C64.1 C66.1 C68.1 C71.2 C72.1 C91.2 C92.2 C130.2 C131.2 C263.2 C270.2 C333.1 FB3.1 L9.1 OL1.1 OU1.5(value) Q4.4(S1) Q4.7(S2) R11.1 U11.6(value) U28.E9(value) U28.F11(value) U28.F13(value) U28.H16(value) U28.J15(value) U28.J16(value) U28.L6(value) U28.M5(value) U28.M6(value) U28.P15(value) U28.P16(value) U28.R7(value) U28.R10(value) U28.T9(value) U28.T10(value)
PWRON: ED25.1 J3.4 R12.2 TP61.1(TP)
RED: D40.2(CATHODE) R475.1
RED_LED: R479.2 U1.W6(value)
REXT: R8.1 U1.W13(value)
RX0_INT: U1.A13(value)
RX-I2S-BCLK: U28.N1(value)
RX-I2S-DIN: U28.L2(value)
RX-I2S-LRCK: U28.M2(value)
RX-I2S-MCLK: U28.T1(value)
SA0: DU1.R2(value) U1.N4(value)
SA1: DU1.P2(value) U1.M5(value)
SA2: DU1.N2(value) U1.M4(value)
SA3: DU1.N3(value) U1.L3(value)
SA4: DU1.M3(value) U1.K3(value)
SA5: DU1.F3(value) U1.J3(value)
SA6: DU1.E3(value) U1.H2(value)
SA7: DU1.E2(value) U1.H3(value)
SA8: DU1.D2(value) U1.G3(value)
SA9: DU1.C2(value) U1.G4(value)
SCK: DR3.2 DU1.J3(value) U1.J1(value)
SCKB: DR3.1 DU1.J2(value) U1.J2(value)
SCKE0: DU1.K3(value) U1.J4(value)
SCKE1: DU1.K4(value) U1.J5(value)
SCS0: DU1.L3(value) U1.K2(value)
SCS1: DU1.L4(value) U1.K4(value)
SDC0-CLK: D18.1(ANODE) J8.5(value) R125.2
SDC0-CMD: D19.1(ANODE) J8.3(value) R122.2 U1.W4(value)
SDC0-D0: D17.1(ANODE) J8.7(value) U1.Y4(value)
SDC0-D1: D16.1(ANODE) J8.8(value) U1.Y5(value)
SDC0-D2: D15.1(ANODE) J8.1(value) U1.Y3(value)
SDC0-D3: D20.1(ANODE) J8.2(value) U1.AA3(value)
SDC0-DET: D21.1(ANODE) J8.9(value) R123.2 U1.AA2(value)
SDQ0: DU1.P9(value) U1.R2(value)
SDQ1: DU1.N9(value) U1.R1(value)
SDQ2: DU1.N10(value) U1.P2(value)
SDQ3: DU1.N11(value) U1.N3(value)
SDQ4: DU1.M8(value) U1.M1(value)
SDQ5: DU1.M9(value) U1.M2(value)
SDQ6: DU1.M10(value) U1.M3(value)
SDQ7: DU1.M11(value) U1.L2(value)
SDQ8: DU1.R9(value) U1.Y1(value)
SDQ9: DU1.R8(value) U1.W2(value)
SDQ10: DU1.T8(value) U1.W1(value)
SDQ11: DU1.T9(value) U1.V3(value)
SDQ12: DU1.R10(value) U1.U2(value)
SDQ13: DU1.T10(value) U1.T3(value)
SDQ14: DU1.T11(value) U1.T2(value)
SDQ15: DU1.R11(value) U1.T1(value)
SDQ16: DU1.F8(value) U1.E2(value)
SDQ17: DU1.F9(value) U1.D2(value)
SDQ18: DU1.E9(value) U1.D1(value)
SDQ19: DU1.F10(value) U1.D3(value)
SDQ20: DU1.F11(value) U1.A2(value)
SDQ21: DU1.D9(value) U1.B2(value)
SDQ22: DU1.E10(value) U1.B1(value)
SDQ23: DU1.E11(value) U1.A3(value)
SDQ24: DU1.B11(value) U1.A4(value)
SDQ25: DU1.C10(value) U1.B4(value)
SDQ26: DU1.C11(value) U1.C4(value)
SDQ27: DU1.B10(value) U1.B5(value)
SDQ28: DU1.B9(value) U1.C6(value)
SDQ29: DU1.B8(value) U1.A7(value)
SDQ30: DU1.C8(value) U1.B8(value)
SDQ31: DU1.C9(value) U1.B7(value)
SDQM0: DU1.L8(value) U1.R3(value)
SDQM1: DU1.P8(value) U1.Y2(value)
SDQM2: DU1.G8(value) U1.F3(value)
SDQM3: DU1.D8(value) U1.B3(value)
SDQS0: DU1.L10(value) U1.N1(value)
SDQS0B: DU1.L11(value) U1.N2(value)
SDQS1: DU1.P10(value) U1.V1(value)
SDQS1B: DU1.P11(value) U1.V2(value)
SDQS2: DU1.G10(value) U1.C1(value)
SDQS2B: DU1.G11(value) U1.C2(value)
SDQS3: DU1.D10(value) U1.B6(value)
SDQS3B: DU1.D11(value) U1.A6(value)
Sensor_vcc: J4700.30(value)
SODT0: DU1.J8(value) U1.E3(value)
SPOLN: C330.1 U28.E2(value)
SPOLP: C328.1 U28.D1(value)
SPORN: U28.D2(value)
SPORP: U28.C1(value)
SVREF: DC7.2 DC8.1 DC9.2 DC20.2 DC21.2 DR1.1 DR7.2 DU1.H4(value) DU1.J11(value) U1.K1(value)
TC-STBY: U1.C10(value)
TOUCH_INT: ED28.1 J9.1 U1.Y18(value)
TOUCH_RST: ED29.1 J9.2 U1.W18(value)
TWI0-SCK: ED32.1 J9.4 J4700.27(value) R497.1 R518.1 U1.U9(value) U1000.3(value)
TWI0-SDA: ED33.1 J9.5 J4700.26(value) R498.1 R517.1 U1.W8(value) U1000.4(value)
TWI1-SCK: R6.1 R519.1 U1.Y8(value) U30.23(value) U100.12(value) U4505.13(value)
TWI1-SDA: R7.1 R520.1 U1.AA7(value) U30.24(value) U100.2(value) U4505.14(value)
UART0-RX: U1.D9(value)
UART0-TX: U1.A9(value)
UBOOT: D38.1(ANODE) SW8.1 U1.U15(value)
USB1-DRVVBUS: U1.Y17(value)
USB-5V: C93.2 C94.2 C182.2 OD1.2 R22.1 U19.5(IN)
USB-DM0: D31.1(ANODE) U1.W20(value) USB1.2(value)
USB-DM1: U1.AA20(value)
USB-DP0: D30.1(ANODE) U1.W21(value) USB1.3(value)
USB-DP1: U1.Y20(value)
USB-DRVVBUS: R139.2 U19.4(EN) U28.T16(value)
USB-ID: R140.1 U1.N20(value)
USBVBUS: C183.2 C184.2 C266.2 D36.1(ANODE) R463.2 U19.1(OUT) U28.R16(value) USB1.1(value)
VLED+: C132.2 C133.2 D12.2 OLED1.32(value) OLED1.33(value) TP41.1(TP) U11.5(value)
VLED-: OLED1.34(value) OLED1.35(value) R85.2 R87.1 R1003.1 TP42.1(TP)
VOL+: ED27.1 J3.2 R132.1
VOL-: ED26.1 J3.1 R132.2 R133.1
WHITE: D39.2(CATHODE) R476.1
WHITE_LED: R477.1 U1.V6(value)
WIFI-ANT: ANT1.1 C247.1 R318.1
WL-PMU-EN: R187.2 R191.1 U24.12(value)
WL-SDIO-CLK: C315.2 R195.1 U1.K17(value)
WL-SDIO-CMD: C314.2 R176.2 U1.K18(value) U24.16(value)
WL-SDIO-D0: C316.2 R174.2 U1.L19(value) U24.18(value)
WL-SDIO-D1: C317.2 R173.2 U1.M16(value) U24.19(value)
WL-SDIO-D2: C312.2 R178.2 U1.M17(value) U24.14(value)
WL-SDIO-D3: C313.2 R177.2 U1.M18(value) U24.15(value)
WL-WAKE-AP: U24.13(value)
X24MI: C28.2 U1.U12(value) X1.1(value)
X24MO: R5.2 U1.V13(value)
X32KI: C232.2 R169.2 U28.B9(value) X2.2
X32KO: C233.2 R169.1 U28.A10(value) X2.1
XTAL-IN: R184.2 U24.10(value)
XTAL-OUT: R185.1 U24.11(value)
N03126: DR2.2 DU1.B3(value)
N03128: DR4.2 DU1.B4(value)
N17860835: C235.2 U24.2(value)
N17860908: R196.2 U24.24(value)
N17860913: L10.2 U24.21(value)
N17860915: R192.1 R466.2 U24.29(value)
N17860923: R195.2 U24.17(value)
N17860980: C241.1 R183.2 R185.2 Y1.3
N17861369: R183.1 R184.1 R186.1
N17861416: C242.1 L10.1 U24.23(value)
N17861480: C240.1 R186.2 Y1.1
N20258136: D3.1(ANODE) R18.1
N20498419: C8.1 U1.Y15(value)
N20508570: C31.2 R5.1 X1.3(value)
N21025268: DR5.1 U1.T5(value)
N21042222: C134.2 R88.2 R89.1
N21042253: D12.1 L9.2
N21042265: R85.1 R89.2 U11.3(value)
N21069307: D37.1(ANODE) R136.1 R140.2 USB1.4(value)
N21069496: R137.2 U19.3(ISET)
N21107518: C176.2 D14.1(ANODE) J8.4(value) R121.2
N21149587: OU1.3(value) R22.2 R23.1
N21149589: OD1.1 OL1.2 OU1.1(value)
N21179643: C206.1 C208.1 C212.2 R152.2 U28.C3(value) U28.D3(value) U28.E3(value)
N21179651: C206.2 C208.2 U28.C4(value)
N21179685: C212.1 U28.E1(value)
N21180774: C202.1 U28.F1(value) U28.G1(value)
N21184464: Q4.3(G) U28.T15(value)
N21200318: C235.1 C249.1 R318.2
N21221879: L11.1 U28.K15(value) U28.K16(value)
N21222303: R19.1 U28.R5(value)
N21222388: D1.2(CATHODE) U28.R15(value)
N21222390: D1.1(ANODE) R11.2
N21223043: C67.1 R12.1 U28.M15(value)
N21226147: D2.1(ANODE) R17.1 SW9.1
N21229926: L1.1 U28.L5(value)
N21230780: L2.1 U28.R12(value) U28.T12(value)
N21231924: L3.1 U28.R8(value) U28.R9(value)
N21232804: L5.1 U28.N6(value) U28.P6(value)
N21233677: R14.1 U28.M16(value)
N21233685: L6.1 U28.C14(value) U28.D14(value)
N21233778: L7.1 U28.C12(value) U28.D12(value)
N21360092: C95.2 C96.2 U29.K2(value)
N21360138: R326.2 U29.H6(value)
N21360140: R325.2 U29.T5(value)
N21487734: R28.2 U1.AA12(value)
N21487790: R125.1 U1.AA4(value)
N21839117: Q7.3(C) Q8.1(B) R92.1
N21839131: C136.2 Q8.3(C) R90.2 R91.2 U11.4(value)
N22015419: C51.1 D6.1 L4.2 U6.1(value)
N22015421: C51.2 D5.2 D13.1
N22015458: R9.1 R10.2 U6.3(value)
N22028290: Q18.3(C) R475.2
N22028293: Q17.3(C) R476.2
N22028410: Q17.1(B) R477.2 R478.2
N22029251: Q18.1(B) R479.1 R480.1
N22327296: C4509.1 U4502.4(value)
N22327327: C4506.1 U4500.4(value)
N22327471: C204.1 U14.4(value)
N22328046: OLED1.5(value) T35.1
N22328103: OLED1.37(value) R138.2
N22332510: C217.1 U15.4(value)
N22332561: R127.2 U15.3(value)
N22348396: R1006.2 R1007.1 U1000.1(value)
N22386017: R484.2 R485.1 U100.1(value)
N22386115: R486.2 U101.12(value)
N22386164: C189.2 R488.1 R489.1 U4503.C2(value)
N22386171: TST.1(TP) U4503.A3(value)
N22386468: R483.1 U100.5(value)
N22386474: R482.1 U100.6(value)
N22386496: R126.2 U100.11(value)
N22386590: R487.2 U101.4(value)
N22386600: R128.1 U101.6(value)
N22386644: R481.1 U100.10(value)
N22386973: C292.1 U30.10(value)
N22437552: C328.2 R506.2
N22437762: C329.1 ED2.1 R5122.1 TP69.1(TP)
N22437782: C331.1 ED1.1 R5121.1 TP68.1(TP)
N22437840: C332.1 FB3.2 U103.6(value)
N22437866: R507.1 U103.4(value)
N22437896: C327.2 U103.2(value)
N22437902: R5122.2 U103.5(value)
N22437906: R506.1 U103.3(value)
N22437933: C330.2 R507.2
N22437977: R5121.2 U103.8(value)
N22440849: D29.1(ANODE) FB1.2 J4702.6
N22440857: D27.1(ANODE) FB2.2 J4702.4
N22440958: C211.1 R151.2
N22440960: C209.1 R150.2
N22449236: D39.1(ANODE) R5124.2
N22449247: D40.1(ANODE) R1010.2
N22507754: J4700.2(value) R5117.2
N22507764: J4700.9(value) R5118.2
N22528851: R5132.2 U4505.4(value)
N22528855: R5133.2 U4505.9(value)
N22528886: R5134.2 U4505.3(value)
N22528888: R5135.2 U4505.2(value)
N22649936: Q7.1(B) R93.2

Not connected (* = marked no-connect by the designer): DU1 A1(value) A2(value) A12(value) A13(value) B1(value) B13(value) C4(value) K9(value) R3(value) T1(value) T13(value) U1(value) U2(value) U12(value) U13(value); J4700 24(value) 28(value); J4702 5 7; OLED1 6(value) 9(value) 13(value) 17(value) 21(value) 25(value) 38(value) 39(value); OU1 6(value); U1 AA6(value) B10(value) B11(value) C5(value) C13(value) D4(value) D6(value) D7(value) D10(value) E6(value) E10(value) F1(value) F2(value) F4(value) G1(value) G2(value) G5(value) J18(value) J20(value) J21(value) K19(value) K20(value) K21(value) L20(value) M20(value) M21(value) P3(value) R4(value) R5(value) R18(value) T4(value) U3(value) U7(value) V4(value) V15(value) V16(value) V20(value) V21(value) W5(value) W16(value) Y7(value) Y14(value) Y19(value) Y21(value); U11 1(value); U24 4(value) 5(value) 8(value) 32(value) 35(value) 37(value) 38(value) 39(value) 40(value) 45(value) 46(value) 47(value); U28 A1(value) A2(value) A3(value) A6(value) A7(value) A8(value) B1(value) B2(value) B3(value) B6(value) B7(value) B8(value) C8(value) D15(value) G16(value) H15(value) M1(value) R4(value) R13(value) R14(value) T3(value) T6(value) T13(value); U29 A4(value) A6(value) A9(value) A11(value) AA1(value) AA2(value) AA7(value) AA8(value) AA9(value) AA10(value) AA11(value) AA12(value) AA13(value) AA14(value) AE1(value) AE14(value) AG2(value) AG13(value) AH4(value) AH6(value) AH9(value) AH11(value) B2(value) B13(value) D1(value) D14(value) H1(value) H2(value) H7(value) H8(value) H9(value) H10(value) H11(value) H12(value) H13(value) H14(value) J1(value) J7(value) J8(value) J9(value) J10(value) J11(value) J12(value) J13(value) J14(value) K1(value) K3(value) K5(value) K7(value) K8(value) K9(value) K10(value) K11(value) K12(value) K13(value) K14(value) L1(value) L2(value) L3(value) L4(value) L12(value) L13(value) L14(value) M1(value) M2(value) M3(value) M5(value) M8(value) M9(value) M10(value) M12(value) M13(value) M14(value) N1(value) N2(value) N3(value) N10(value) N12(value) N13(value) N14(value) P1(value) P2(value) P3(value) P10(value) P12(value) P13(value) P14(value) R1(value) R2(value) R3(value) R5(value) R12(value) R13(value) R14(value) T1(value) T2(value) T3(value) T12(value) T13(value) T14(value) U1(value) U2(value) U3(value) U6(value) U7(value) U10(value) U12(value) U13(value) U14(value) V1(value) V2(value) V3(value) V12(value) V13(value) V14(value) W1(value) W2(value) W3(value) W7(value) W8(value) W9(value) W10(value) W11(value) W12(value) W13(value) W14(value) Y1(value) Y3(value) Y6(value) Y7(value) Y8(value) Y9(value) Y10(value) Y11(value) Y12(value) Y13(value) Y14(value); U30 1(value) 2(value) 3(value) 4(value) 5(value) 6(value) 14(value) 15(value) 16(value) 17(value) 19(value); U101 1(value) 5(value); U1000 5(value); U4505 10(value) 11(value)

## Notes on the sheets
sheet 1
- G-SENSOR
- 7Bits I2C Address:
        Gyro
        0x68
- 7Bits I2C Address:
  Accelerometer  Magnetometer
        0x10            0x12
- place PIN1 in the top right, parallel to the screen,
  and put on the top left of the screen
- note: Make sure the routing between the ESD and the
   USB connectors should be on the same PCB side
sheet 2
- CIF Camera
sheet 3
- Touch Panel connector
sheet 4
- POWER TREE
- 5V/1A
- Switch for
  USB Host
- AXP818
- 5V/100mA
- BOOST 5V
- HDMI
- 2.9V-5V/4A
- 4.5W
- PS
- BOOST
- LCD BL
- 1.6V-3.4V/1.5A
- DC/DC1
- 3.1V NAND/EMMC/USB0/CARD/sensor/VCC-IO/PD/AXP818 IO1 (ON)
- 100mΩ from DCDC1
- SWOUT
- 3.1V VCC-LCD (OFF)
- 0.5V-1.3V/3A
- DC/DC2
- 0.9V CPUA (ON)
- 5V/2.5A
- 0.5V-1.3V/3A
- DCIN
- DC/DC3
- 0.9V CPUB (ON)
- 0.5V-1.3V/3A
- DC/DC4
- 0.9V GPU (ON)
- 5V/500mA
- Battery
  Charger
  &
  Power
  Detect
- 0.8V-1.84V/2.5A
- VBUS
- DC/DC5
- 1.2V-1.5V DRAM (ON)
- 0.6V-1.52V/2.5A
- DC/DC6
- 0.9V SYS/USB0/HDMI (ON)
- BAT
- 3.5-4.35V
- DC/DC7
- 0.6V-1.52V/1.5A
- 0.7V-3.3V/500mA
- ALDO1
- 1.8V PD/DSI/MIPI CSI/EFUSE/HDMI (ON)
- ALDO2
- 0.7V-3.3V/300mA
- 1.8V PLL/LPDDR/DRAMPLL/ADC/CPVDD/LDOIN (ON)
- 0.7V-3.3V/200mA
- ALDO3
- 3V AVCC/PL (ON)
- 0.7V-3.3V/500mA
- DLDO1
- 3.1V WIFI IO/VCC-IO2 (OFF)
- 0.7V-4.2V/400mA
- DLDO2
- 2.8V-4.2V VCC-MIPI (OFF)
- 0.7V-3.3V/300mA
- DLDO3
- 2.8V AFVCC-CSI/IOVDD-CSI (OFF)
- 0.7V-3.3V/500mA
- DLDO4
- 2.8V AVDD-CSI (OFF)
- 0.7V-1.9V/400mA
- ELDO1
- 1.2V/1.5V/1.8V DVDD-CSI-R (OFF)
- 0.7V-1.9V/200mA
- ELDO2
- 1.8V VCC-DSI(OFF)
- 0.7V-1.9V/200mA
- ELDO3
- 1.2V/1.5V/1.8V DVDD-CSI-F (OFF)
- FLDO1
- 0.7V-1.45V/300mA
- 1.2V HSIC (OFF)
- 0.7V-1.45V/100mA
- FLDO2
- 0.9V CPUS (ON)
- FLDO3
- 1/2 FLDOIN or
  1/2 DCDC5 /30mA
- 0.7V-3.3V/100mA
- GPIO0/LDO
- 3.1V CTP (OFF)
- 0.7V-3.3V/150mA
- GPIO1/LDO
- 3.1V VIBRATOR (OFF)
- 1.8V/200mA or 3V/60mA
- VCC-RTC
- 1.8V RTC/VDD-1V8/LVDS (ALWAYS ON)
sheet 5
- LPDDR3_32X1
sheet 6
- CPU
- DECOUPLE CAP
- CLK
sheet 7
- PMIC
- BAT
- PS-5V
- connect the USBVBUS to DCIN
  if use usb power only
- IF use the battery temperature sensor: A=NC
  otherwise: A=10k
- Vth < 1.5V
  R < 30m ohm
  VGS < 4.5V
- close to
  PMIC
- Battery
- DCIN
- 0.9V
- CAMERA
- OPTION
- If front & rear cameras have different power up
  timing sequence, please refer to the hardware
  design guide.
- 1.2V
- BB
- MIPI LCD
- 1.2V - 1.5V
- 3.0V
- 1.8V
- 5V
- OPTION
- OPTION
- A
- If PD port use 1.8V
  mount A and NC B
- 3.1V
- B
- If PD port use 3.1V
  mount B and NC A
- For 3g
sheet 8
- NAND-eMMC
- eMMC NAND和TSOP NAND COLAY
- If use eMMC, then NC C
  If use NAND, then Mount C
- eMMC
  NAND
- C
- A
- B
- D
- If use eMMC 5.0, mount D.
  else, NC D.
- close to the power of
  eMMC VCCQ1-VCCQ5
  & NAND
- close to the power of
  eMMC VCC1-VCC4
  & NAND
sheet 9
- MIPI DSI
- Backlight
- R=200mV/I(led)
- Differential pairs
  Z0= 100 ohm
- -5v
- +5v
- MIPI/RGB LCM only
sheet 10
- CARD
- KEY
- 0.21V
- 0.41V
- 0.59V
- 0.74V
- 0.88V
- note: Make sure the routing between the ESD and the
   USB connectors should be on the same PCB side
- OPTION
- 150 mil
- USB OTG
- Differential pairs
  Z0= 90 ohm
- Ilim (A)=6800/Rset (ohm)
sheet 11
- CODEC
- HP_JACK
- 走线宽度至少80MIL
- connect to GND and
  close to HP jack
- The pull up voltage should
   be equaled to VCC-RTC
- Differential Pair
- L
- R
- GND
- MIC
- OSC-RTC
- SPEAKER
- POWER
sheet 12
- SDIO WIFI+BT
- 50 ohm
- A
- close to AP
- B
- Note:
  AP6210，Mount A+C+D+E，NC B+F
  AP6181，Mount B+E，NC A+C+D+F
  8723BS，Mount F，NC A+B+C+D+E
- E
- E
- E
- F
- C
- D
